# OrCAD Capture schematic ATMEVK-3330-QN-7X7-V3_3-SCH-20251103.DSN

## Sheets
1 10. Power Configuration: title: ATM3330e EVALUATION BOARD; rev: 3.3; note: 052-33-610-xxxx
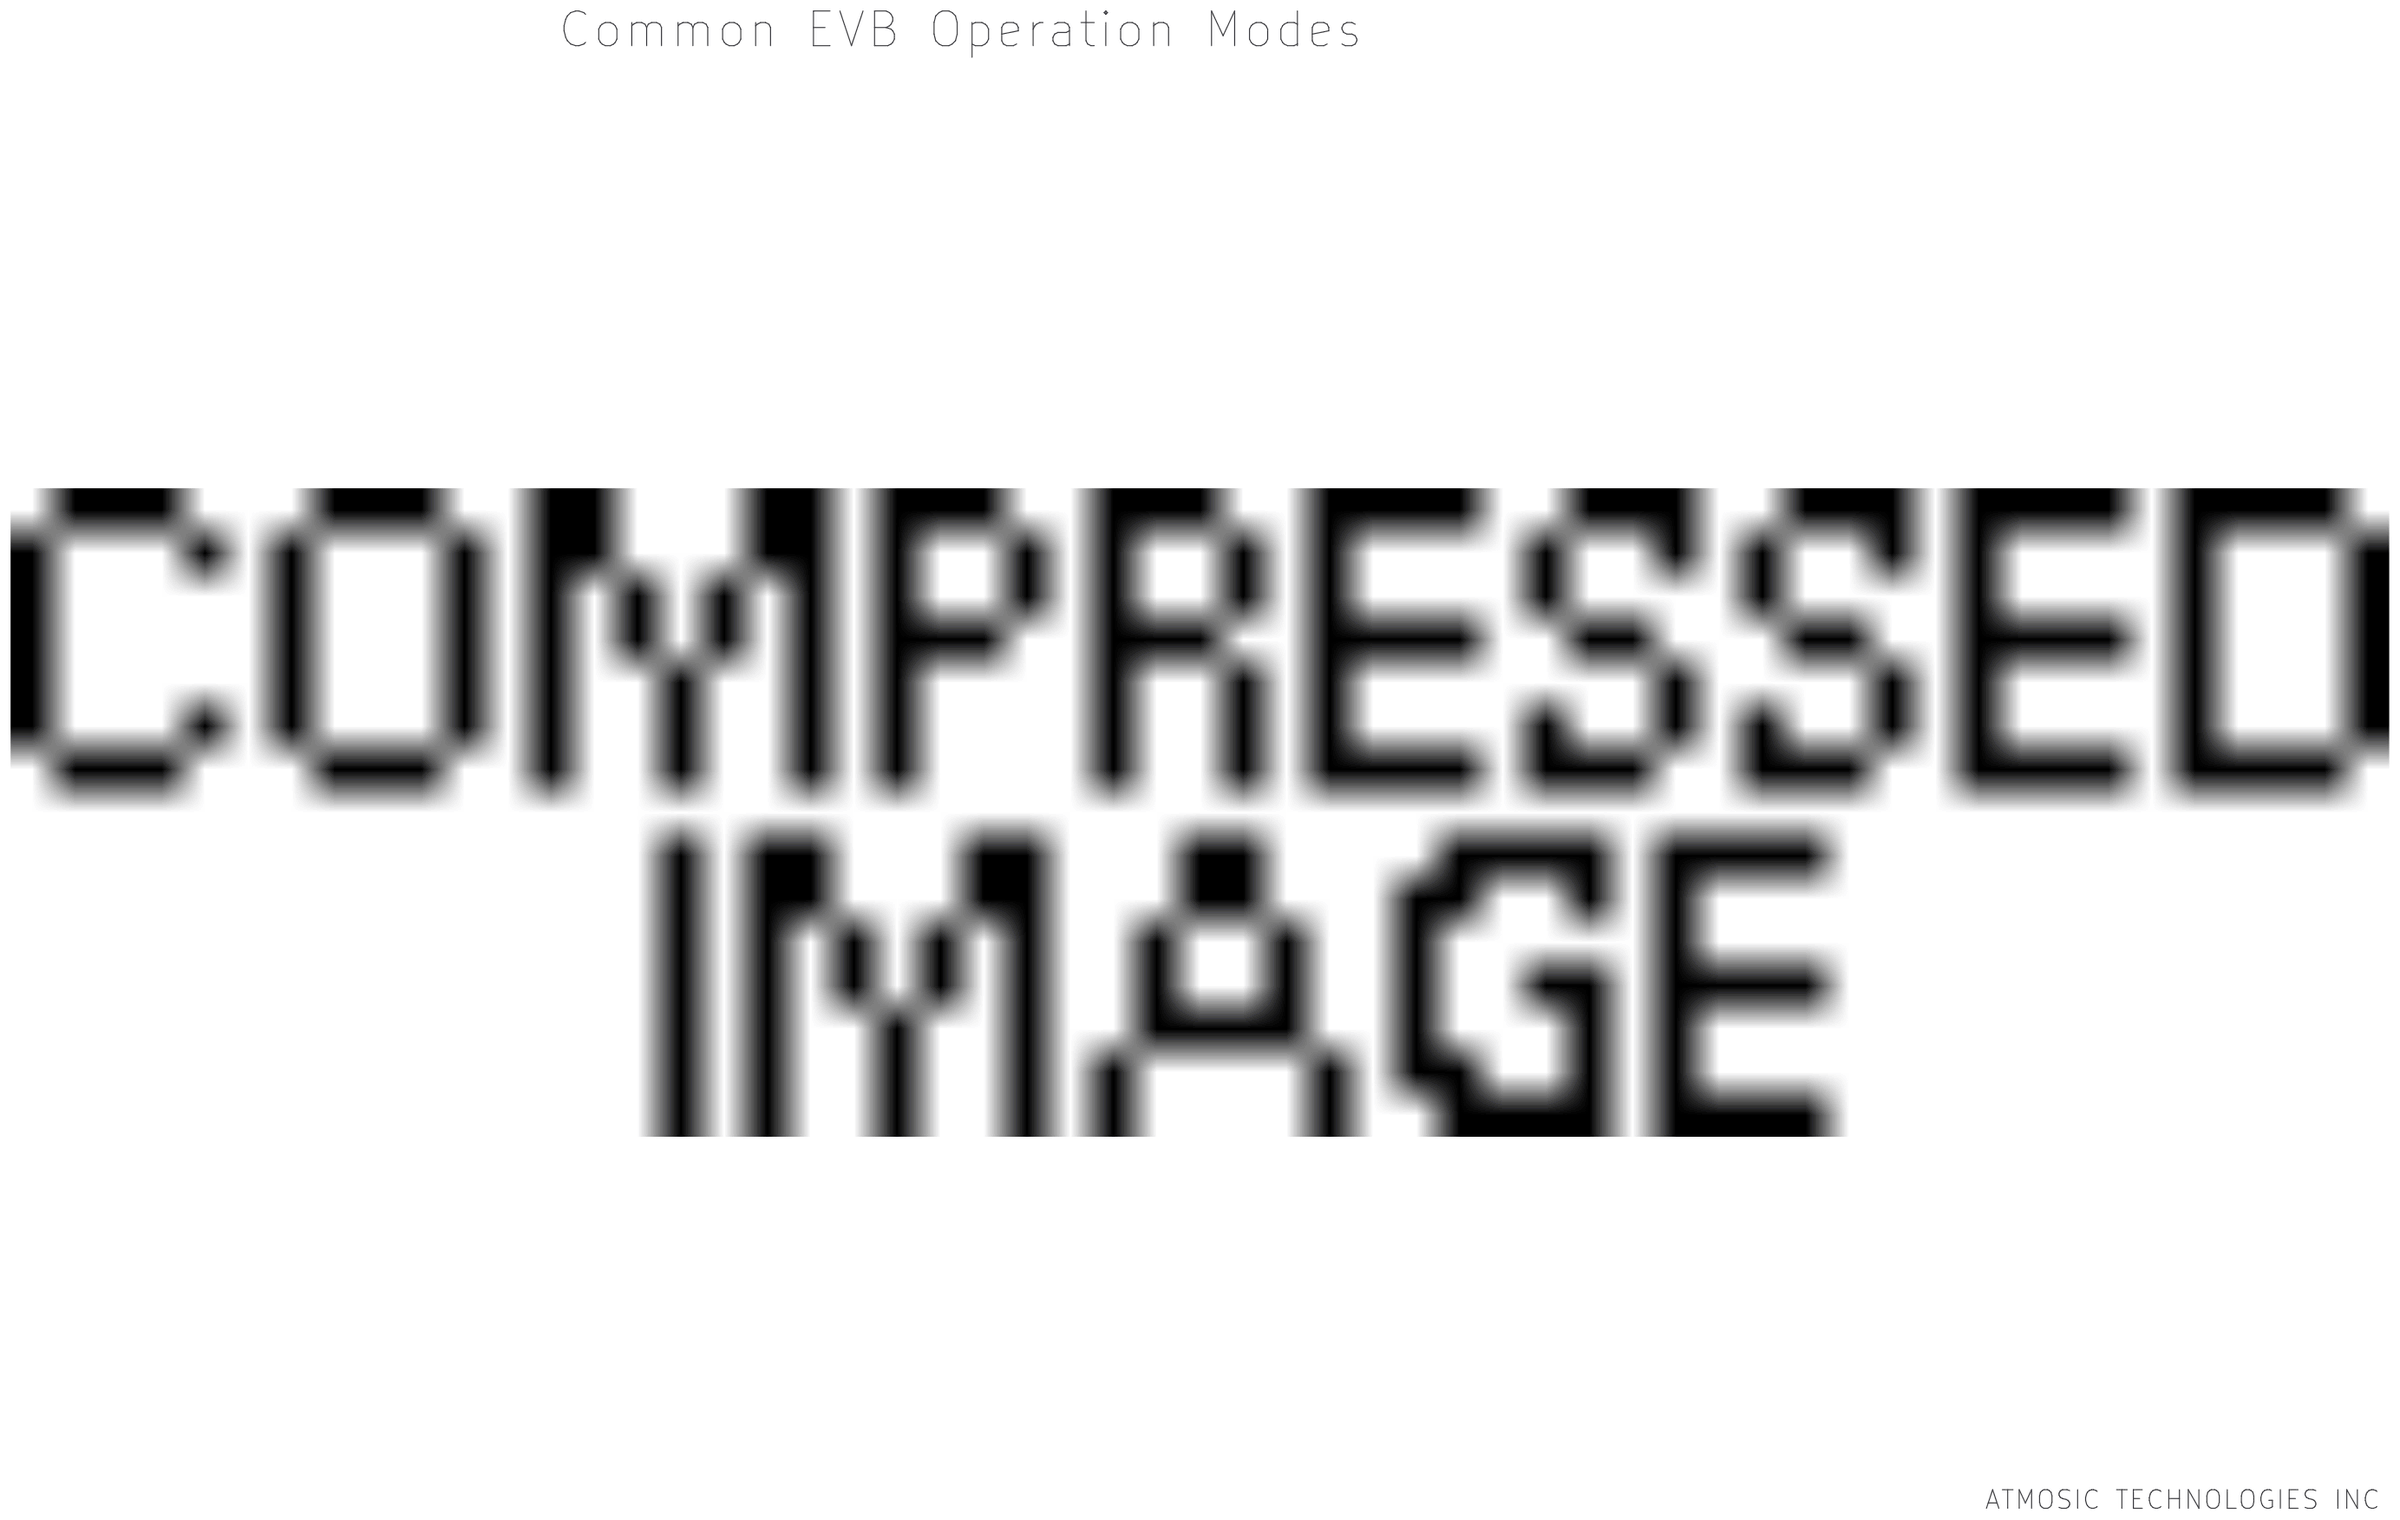
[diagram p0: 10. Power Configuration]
2 01. TITLE
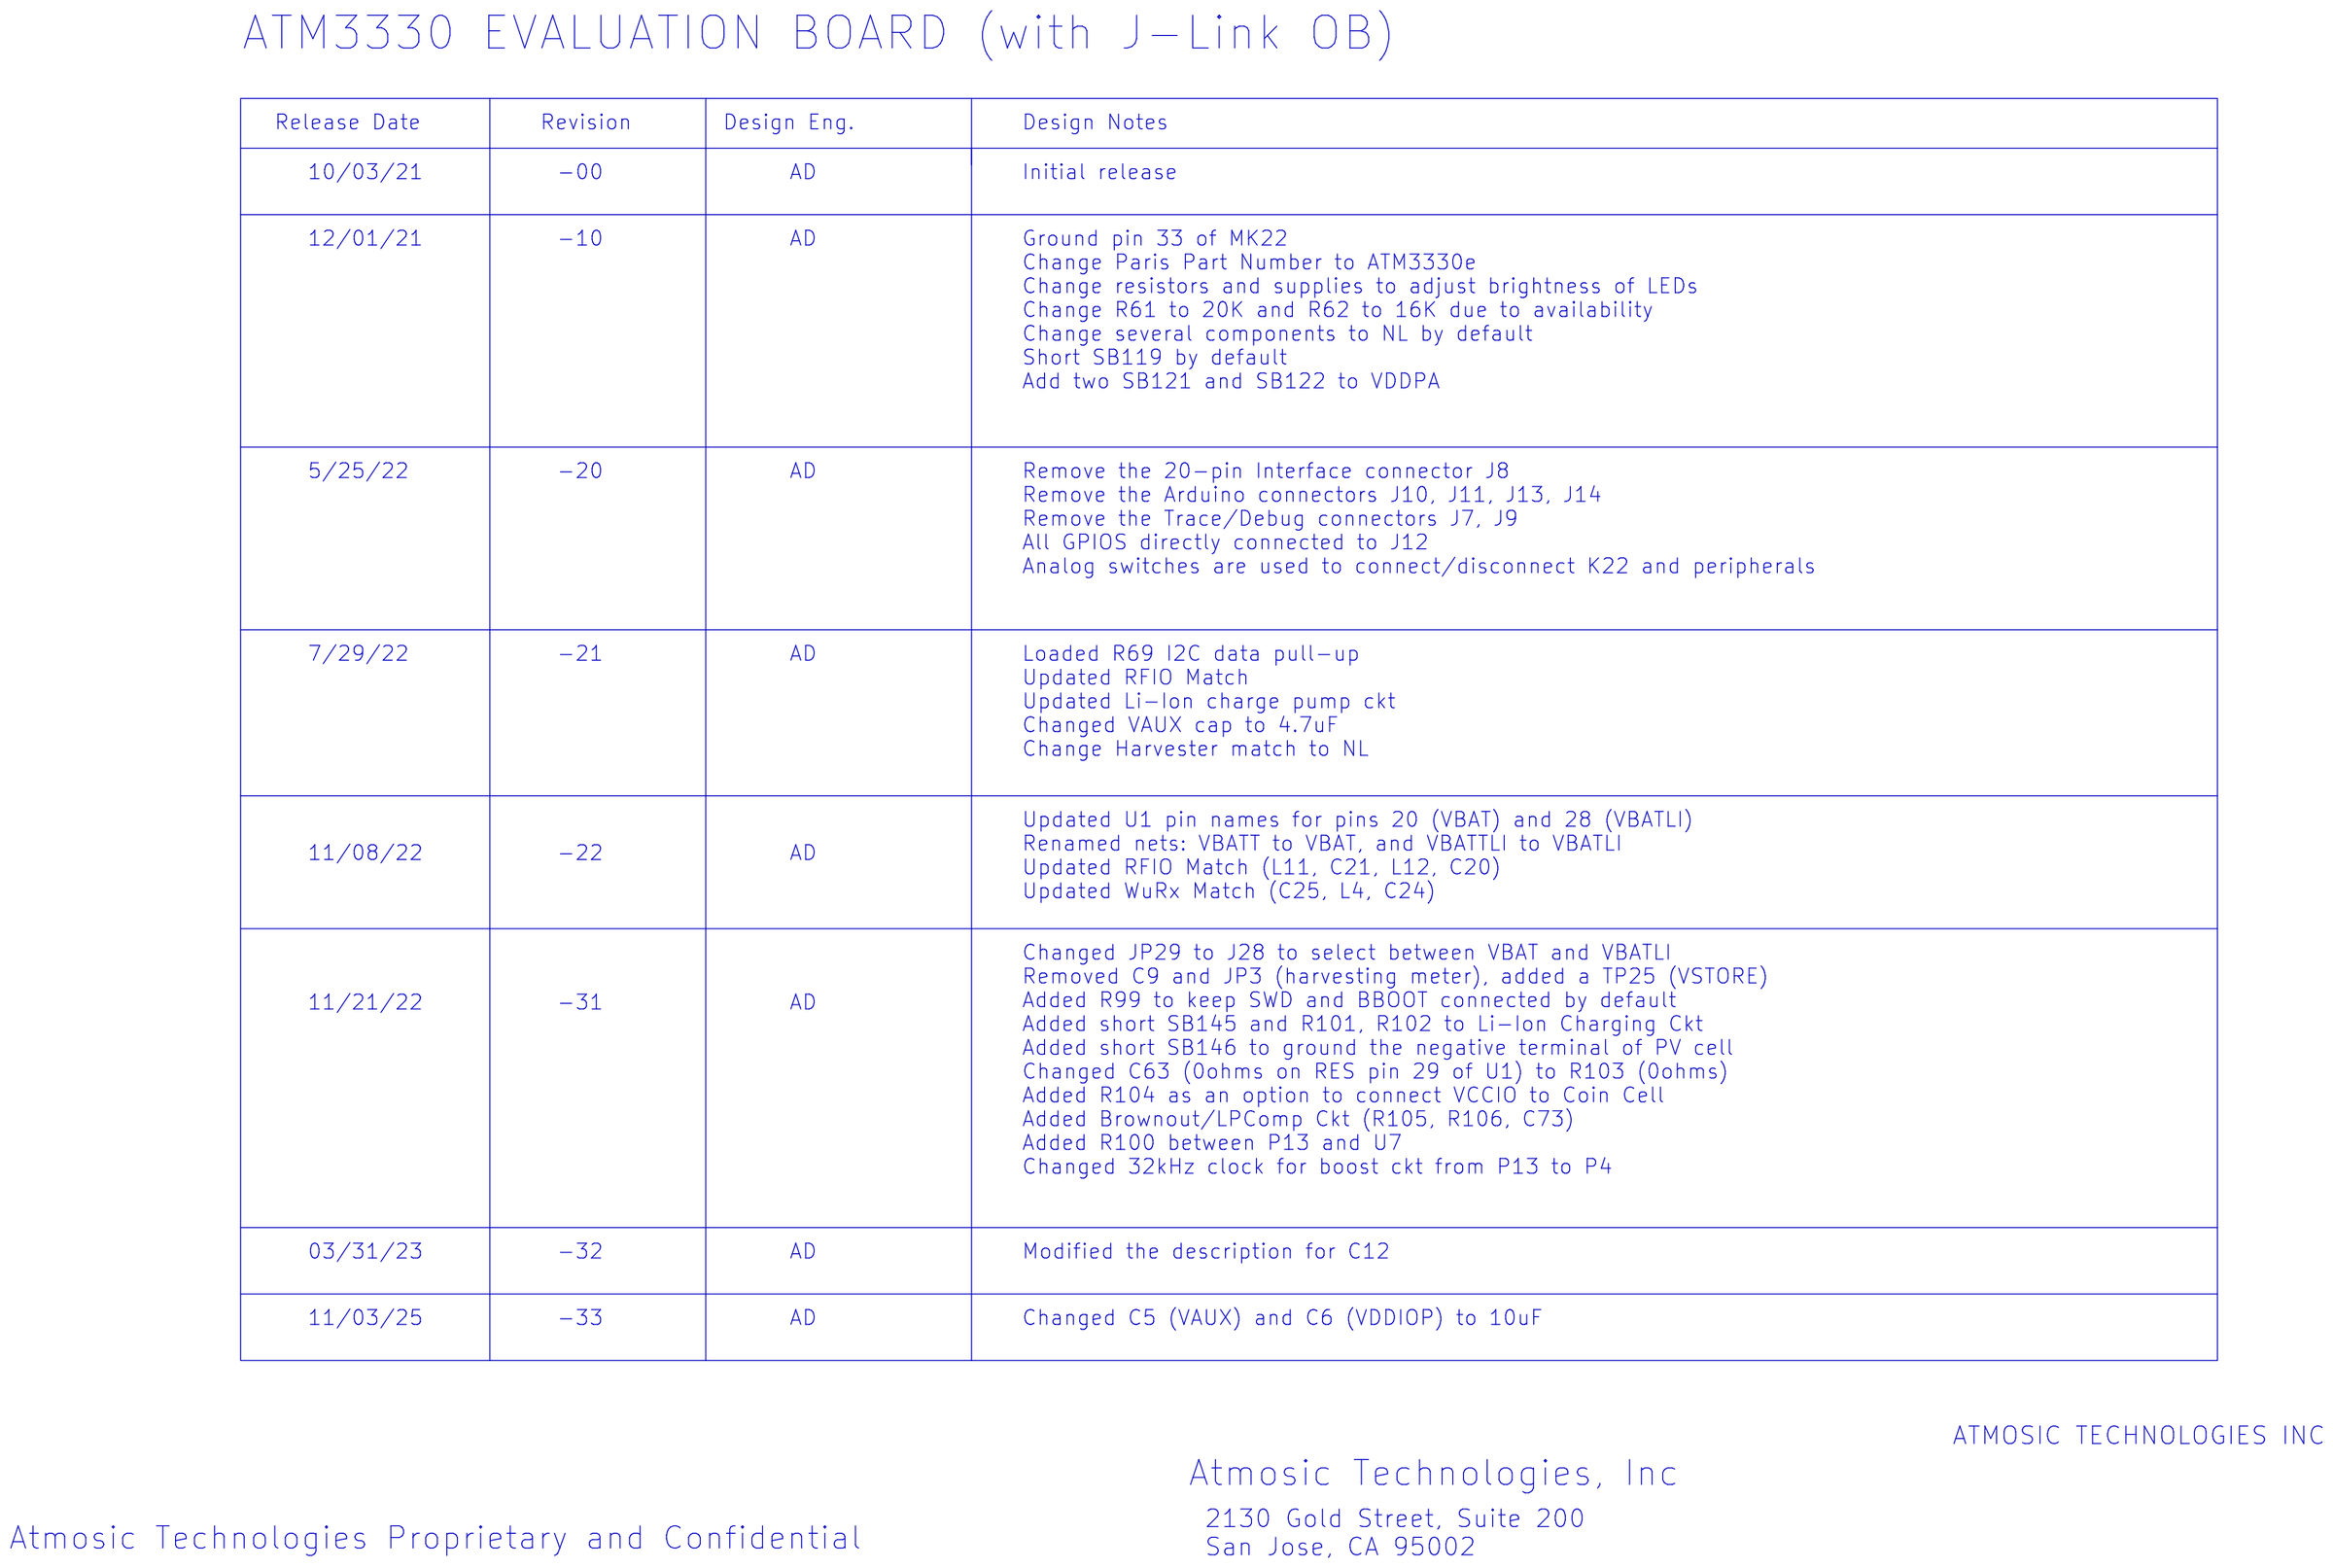
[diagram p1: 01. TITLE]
3 02. Block Diagram
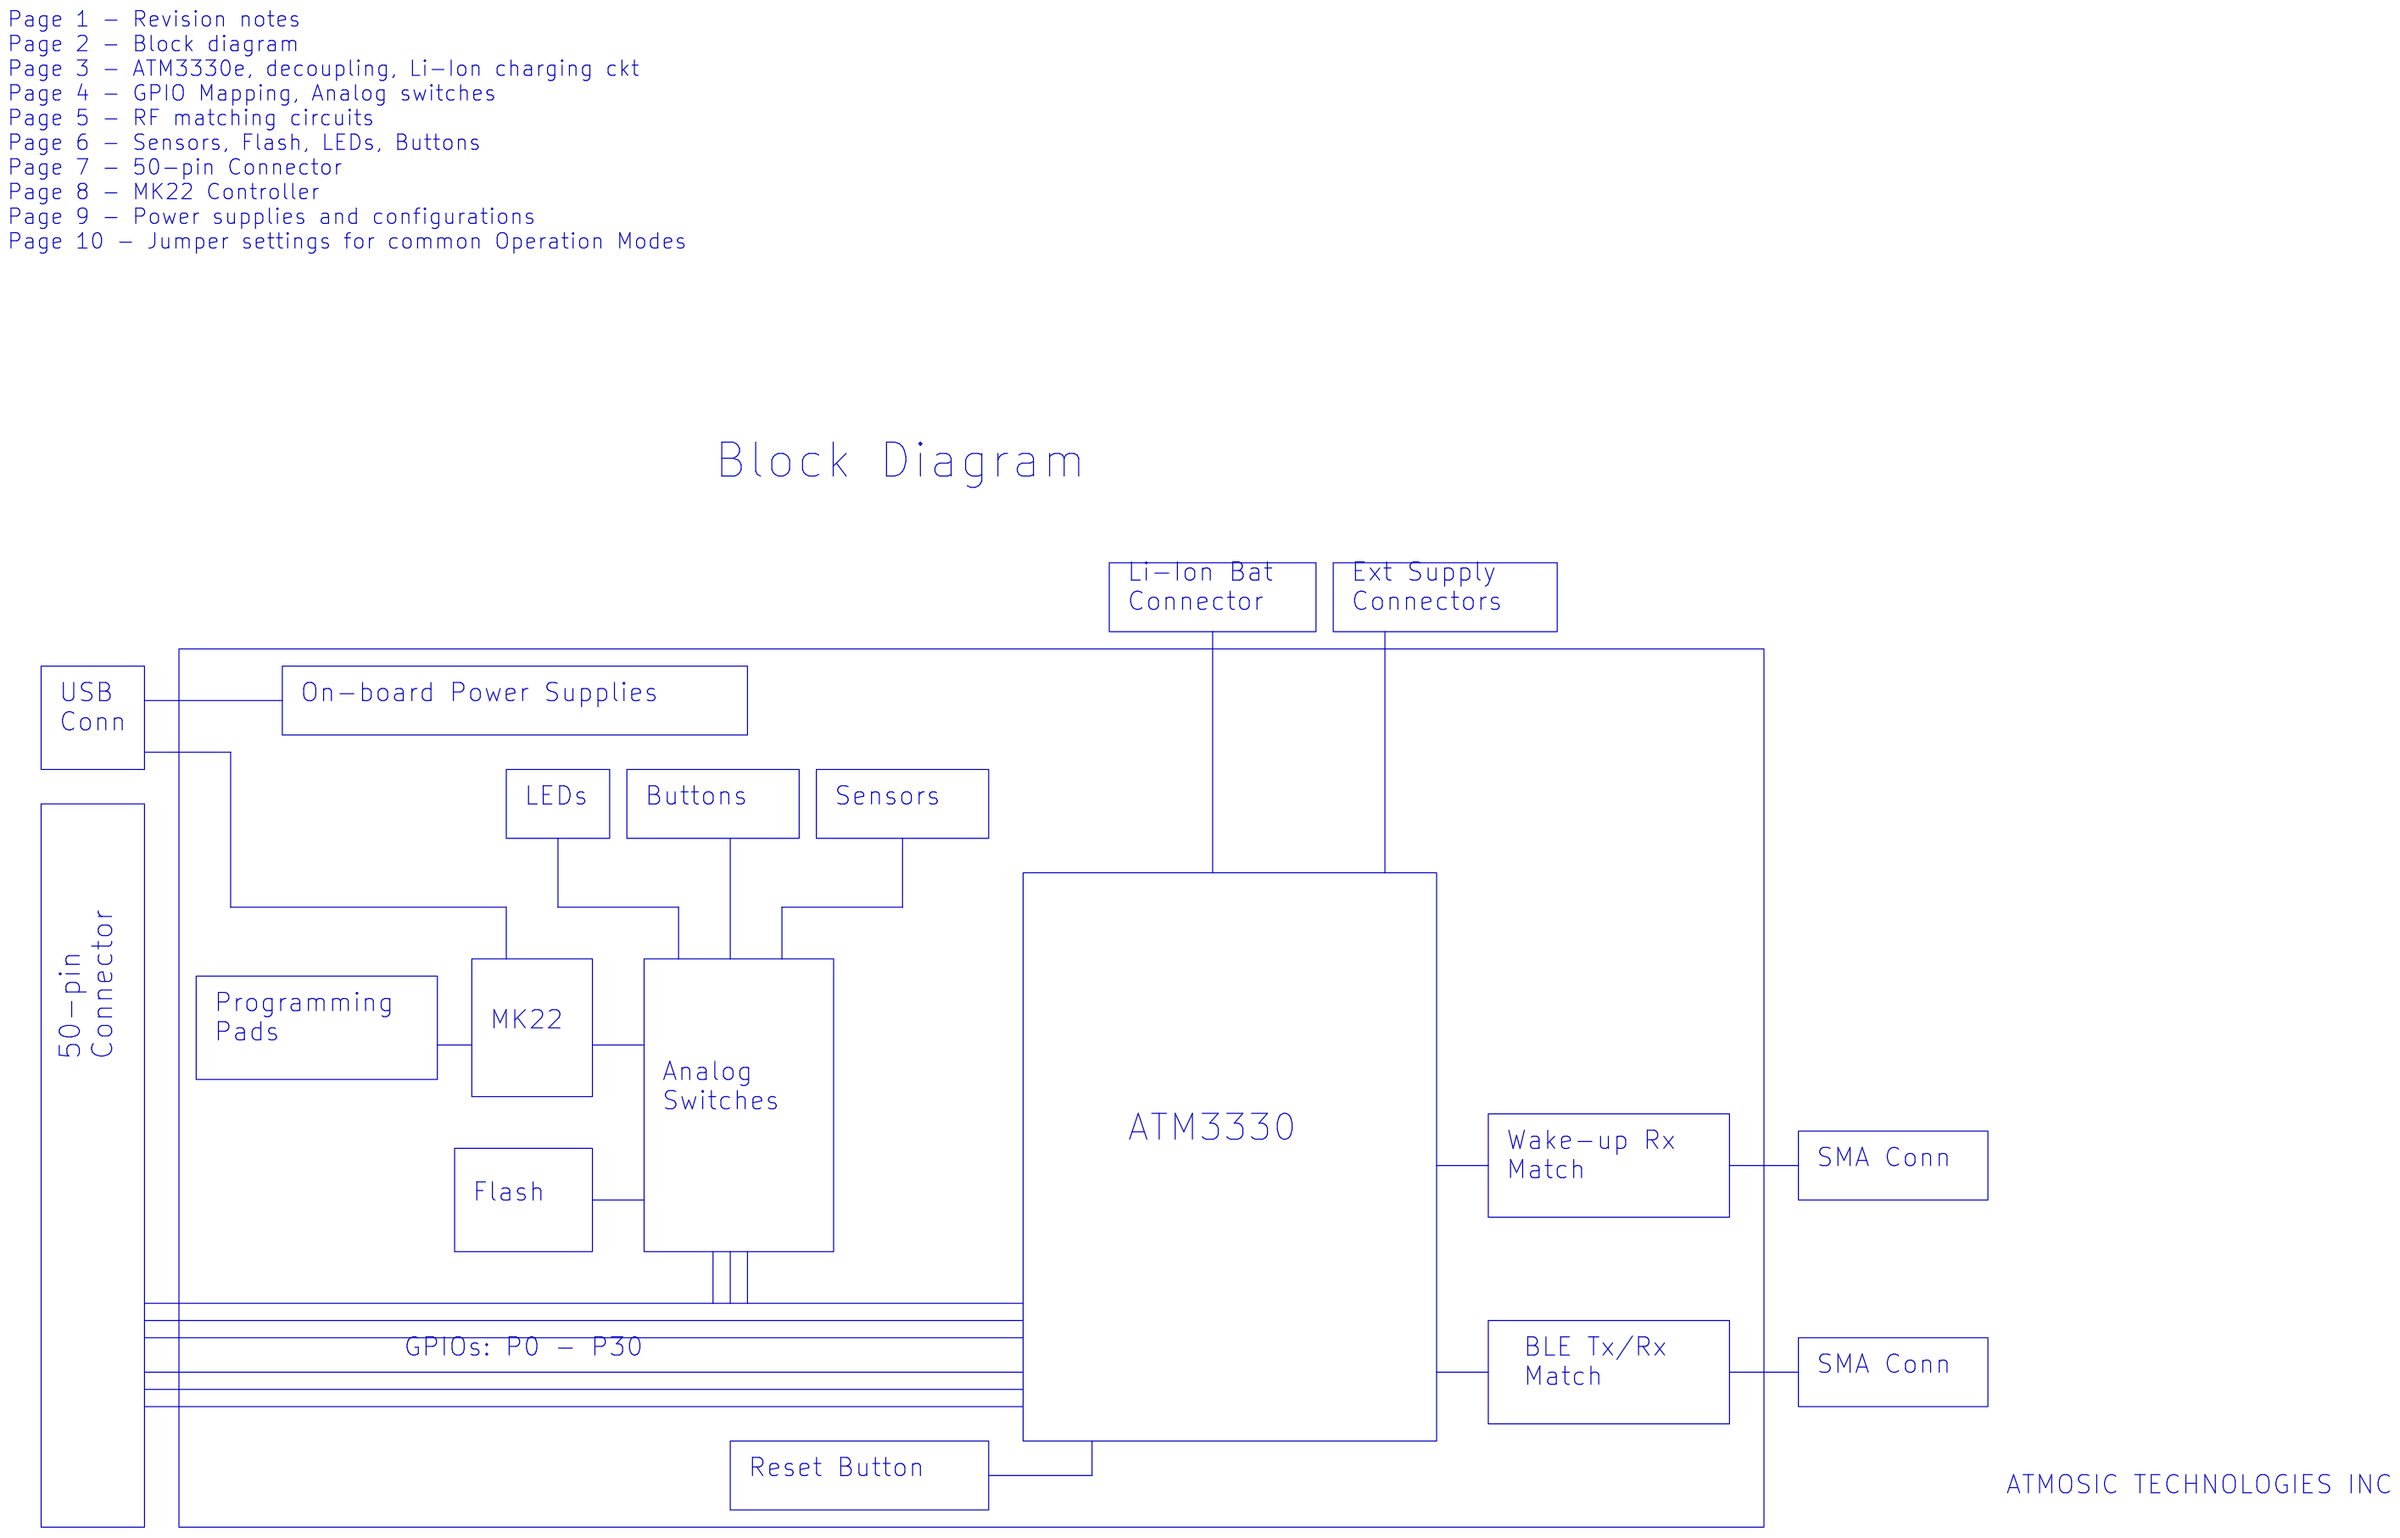
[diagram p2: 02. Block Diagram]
4 03. ATM3330: size B
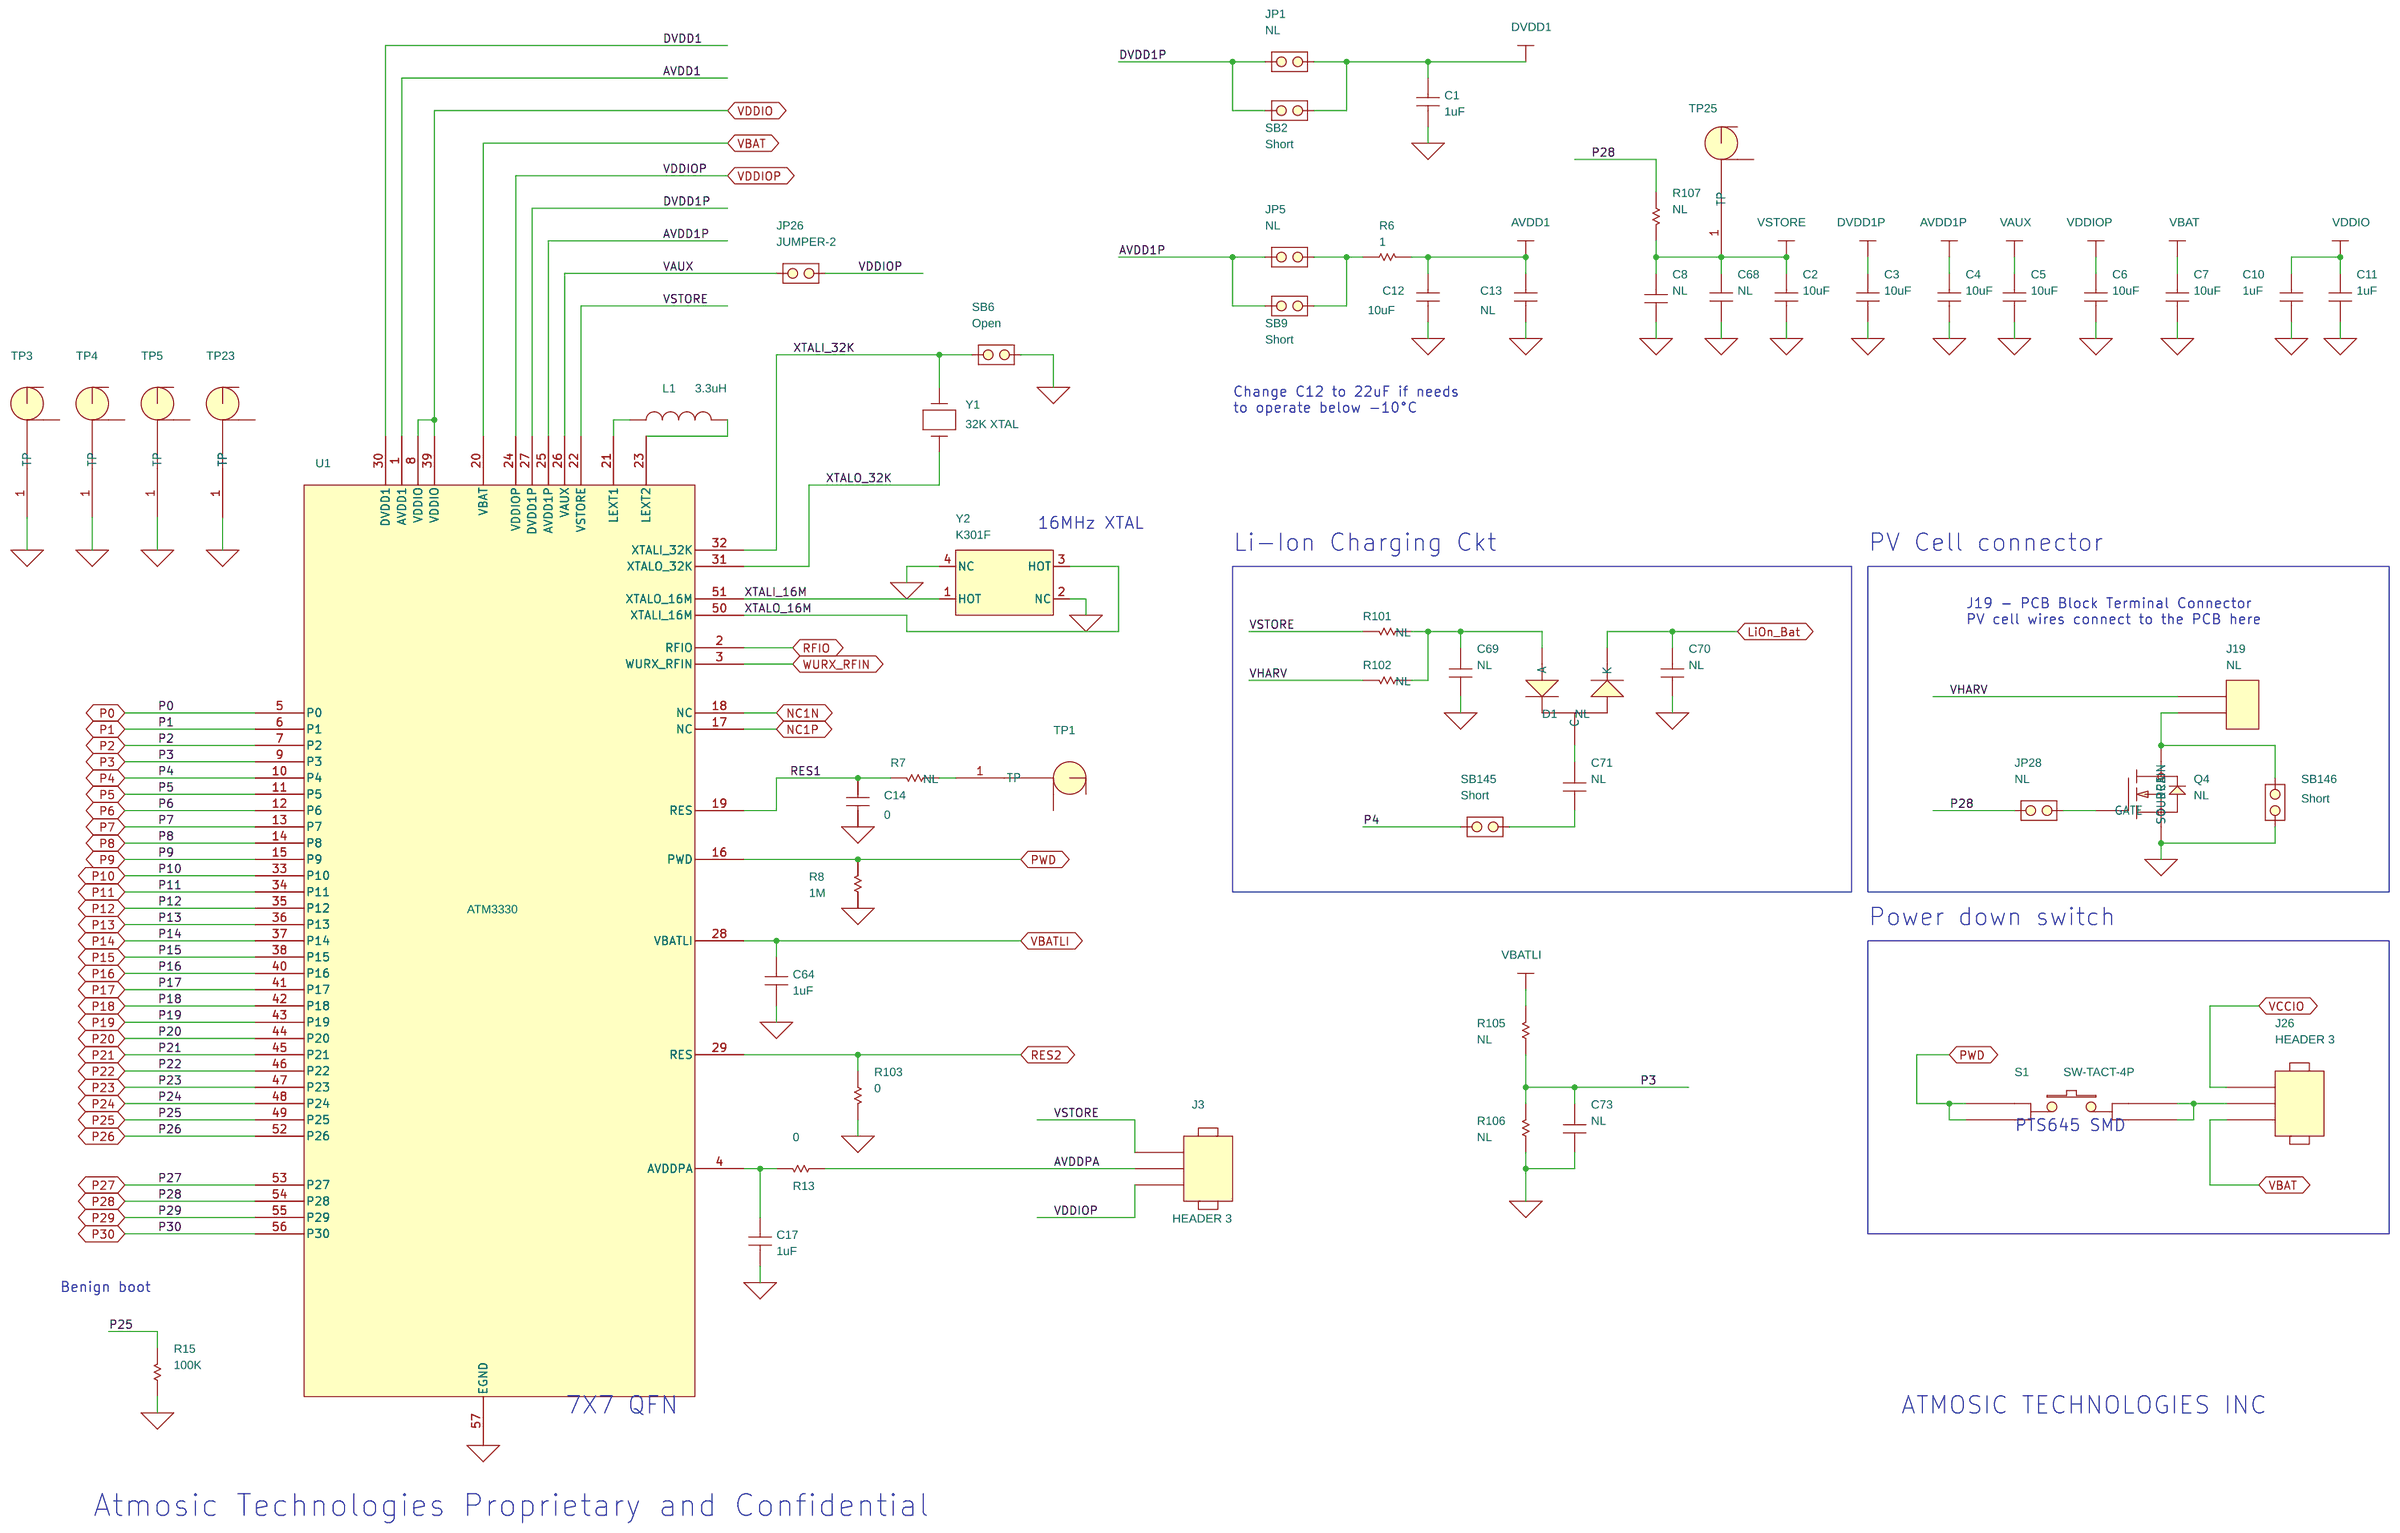
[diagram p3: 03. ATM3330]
5 04. GPIO Mapping: size B
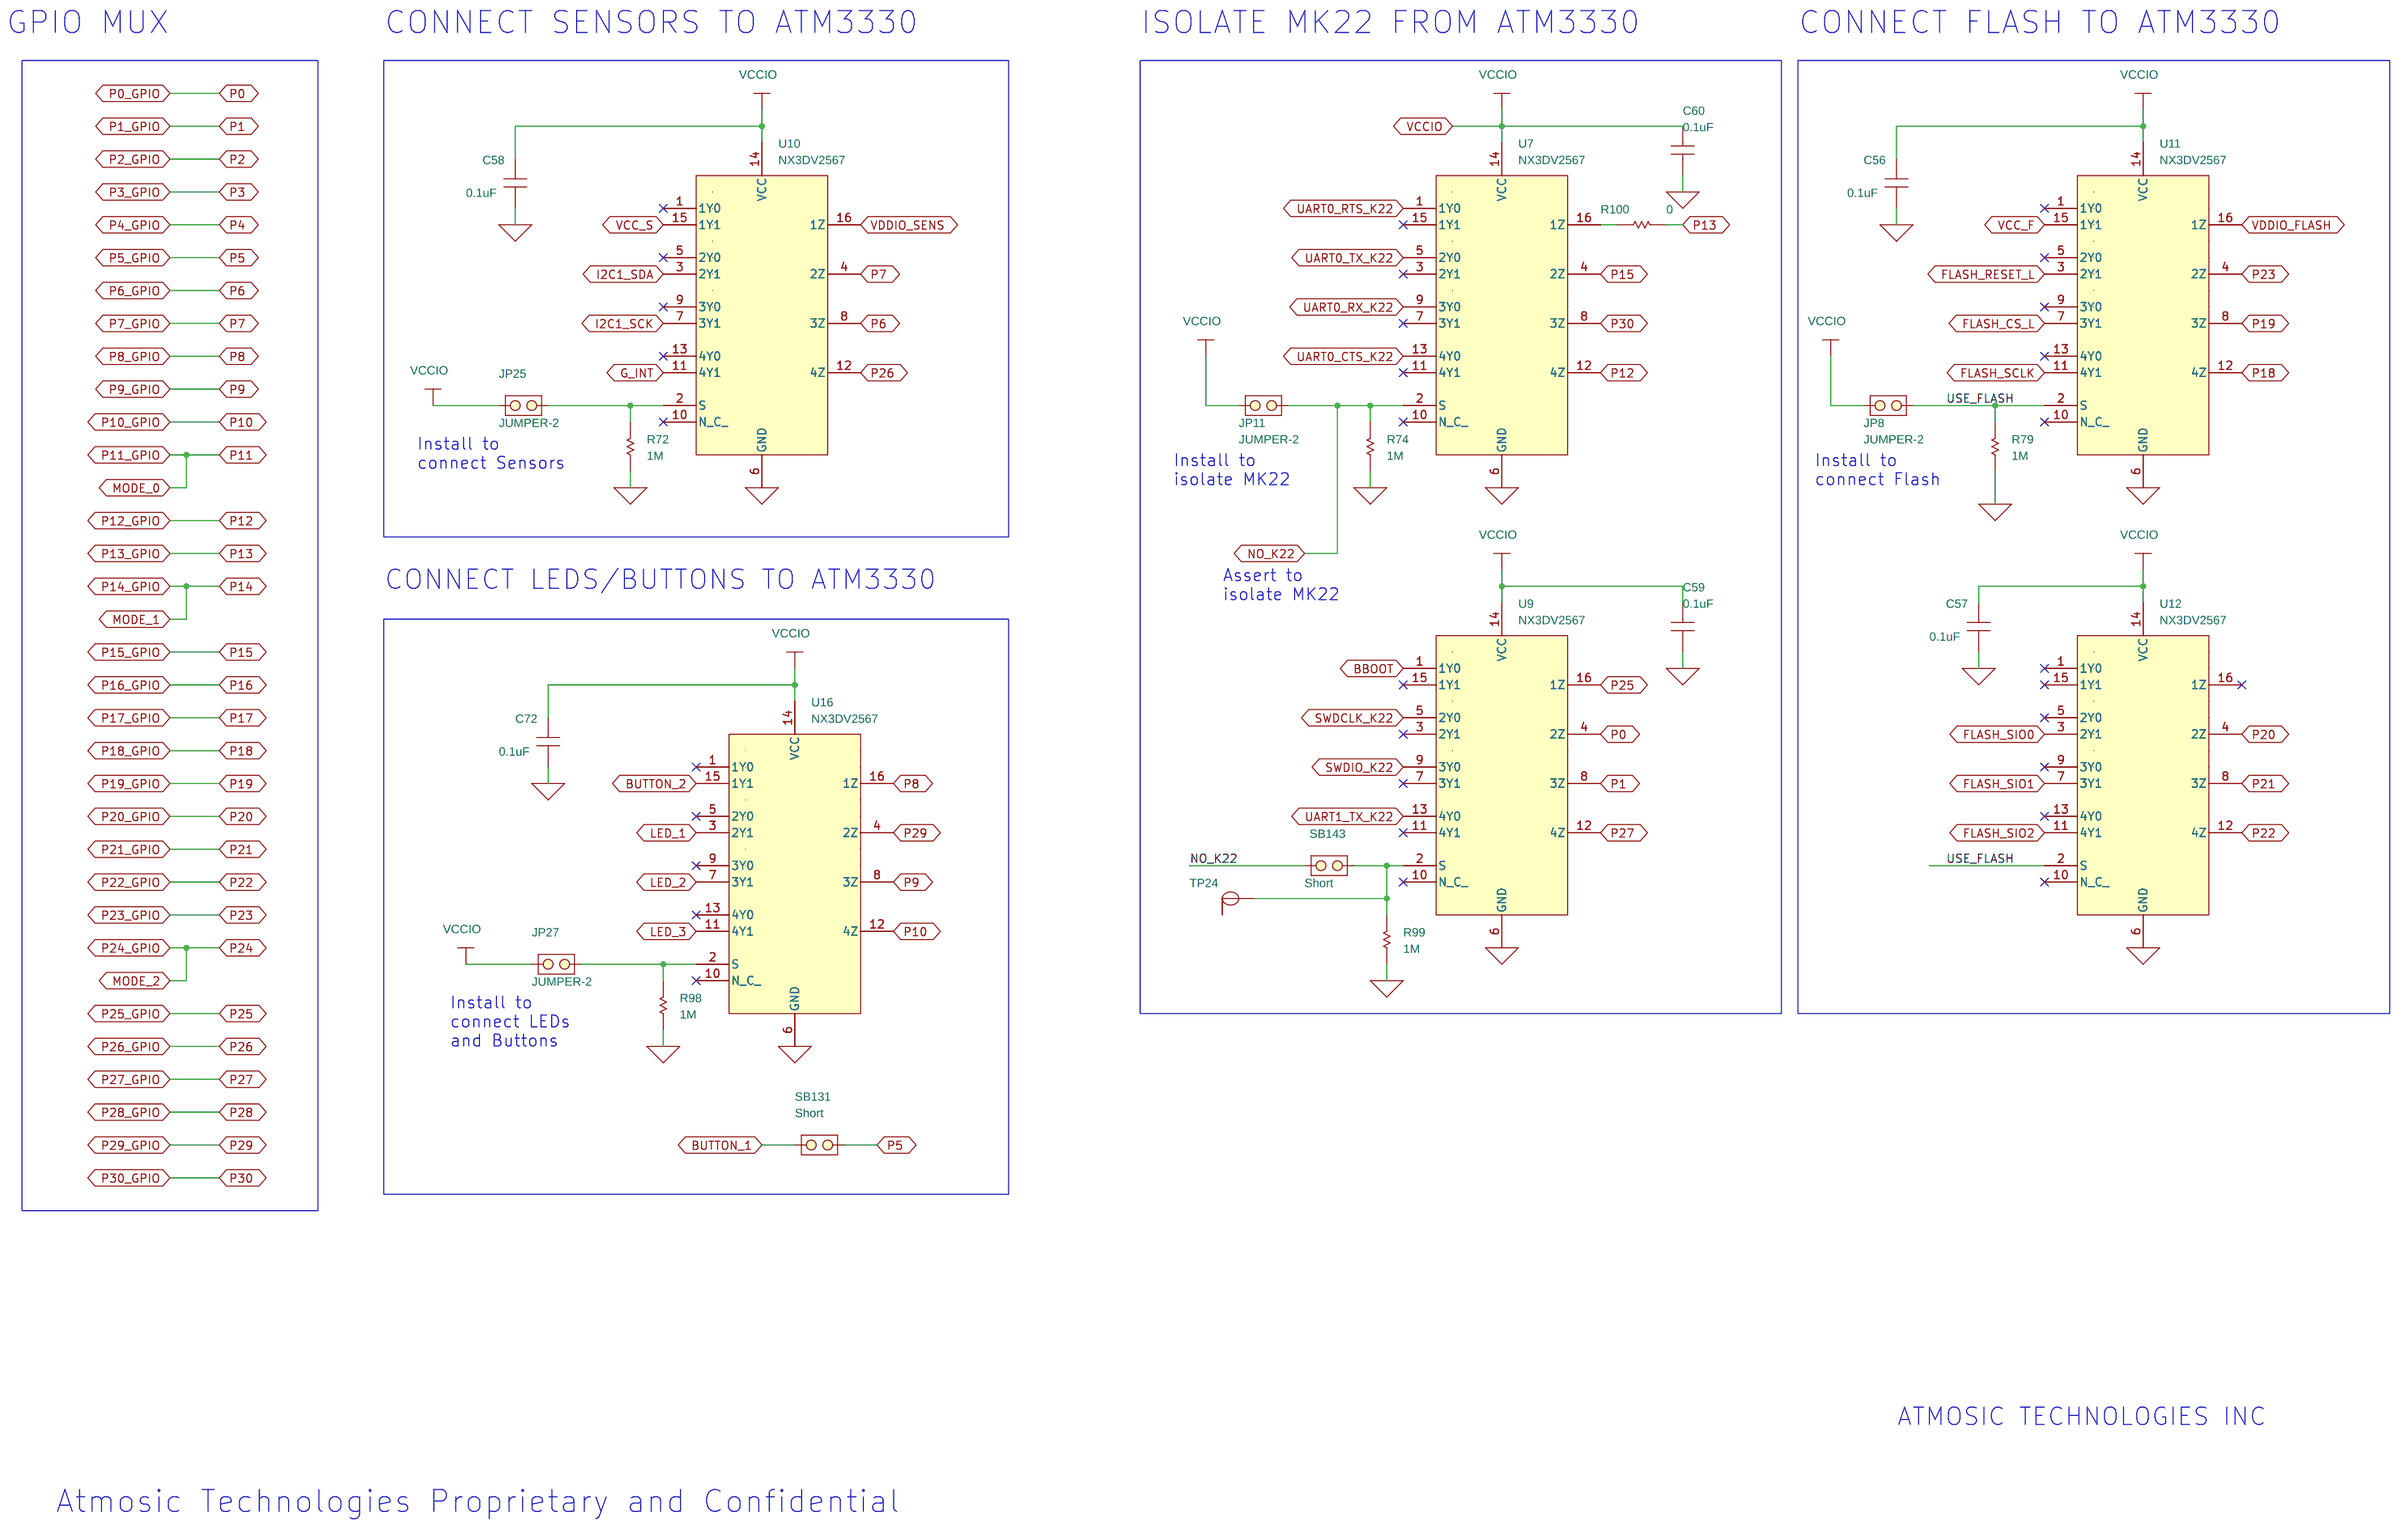
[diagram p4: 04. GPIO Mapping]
6 06. Buttons LEDs Sensors: size B
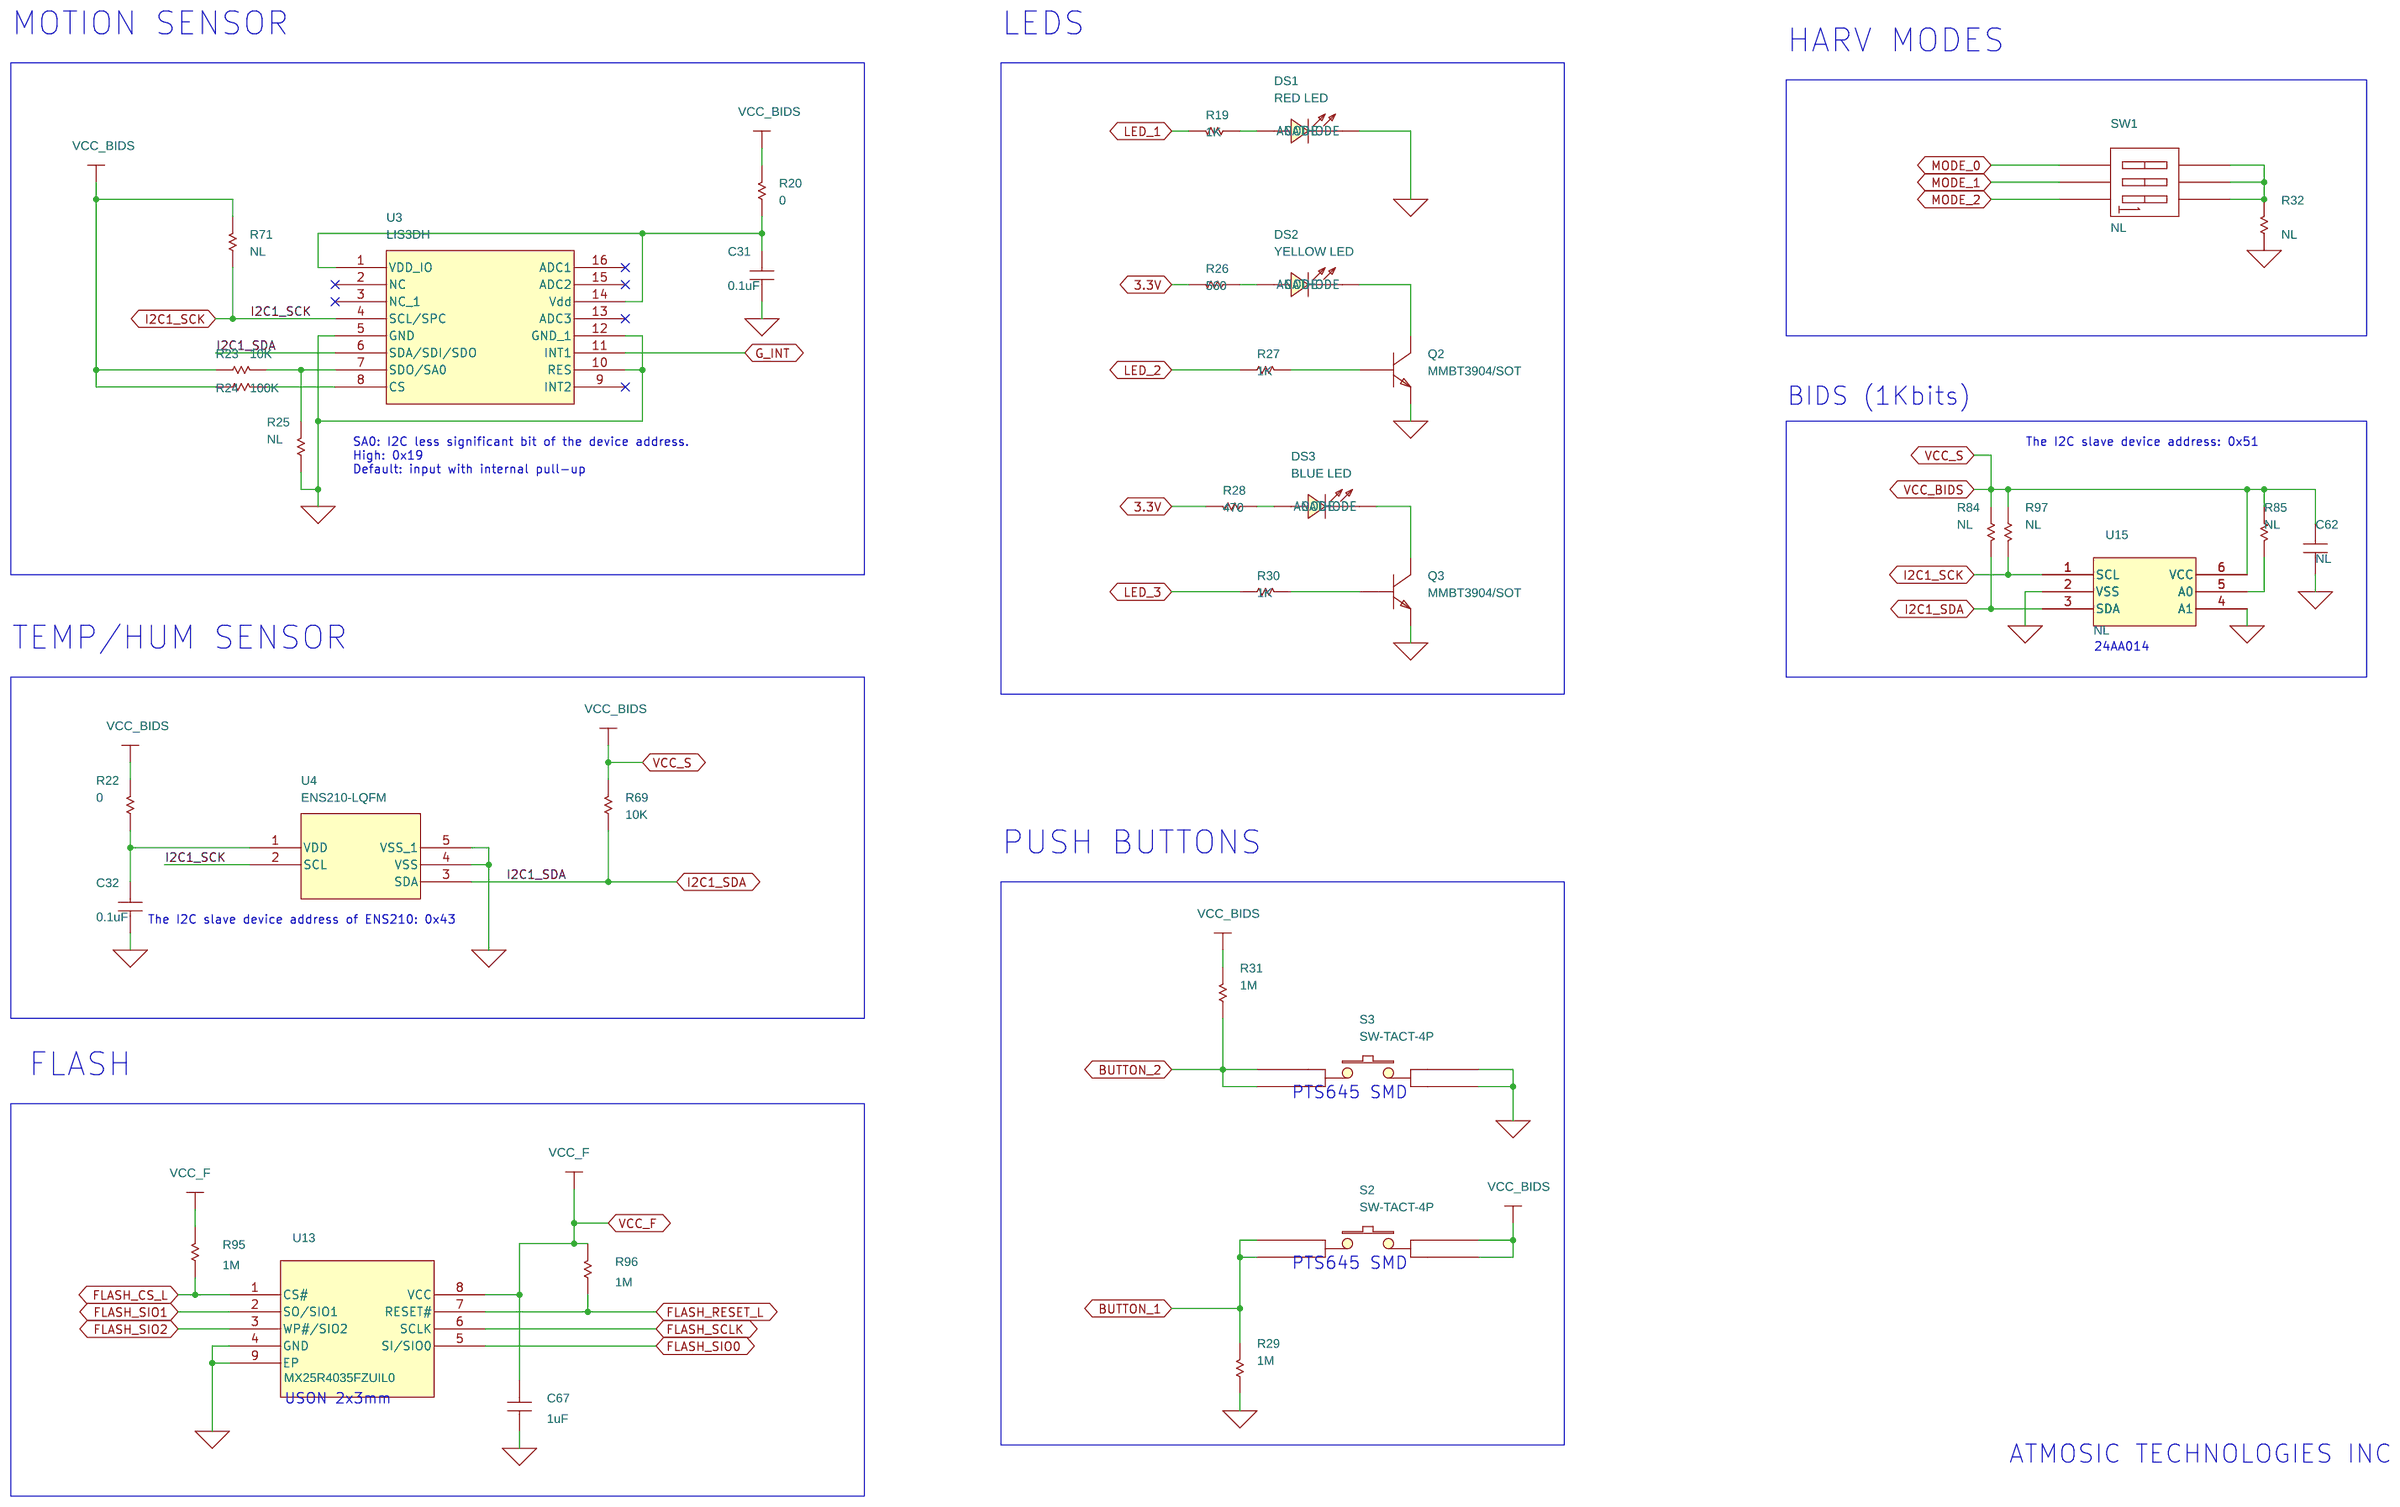
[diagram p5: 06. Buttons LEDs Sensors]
7 07. Connectors: size B
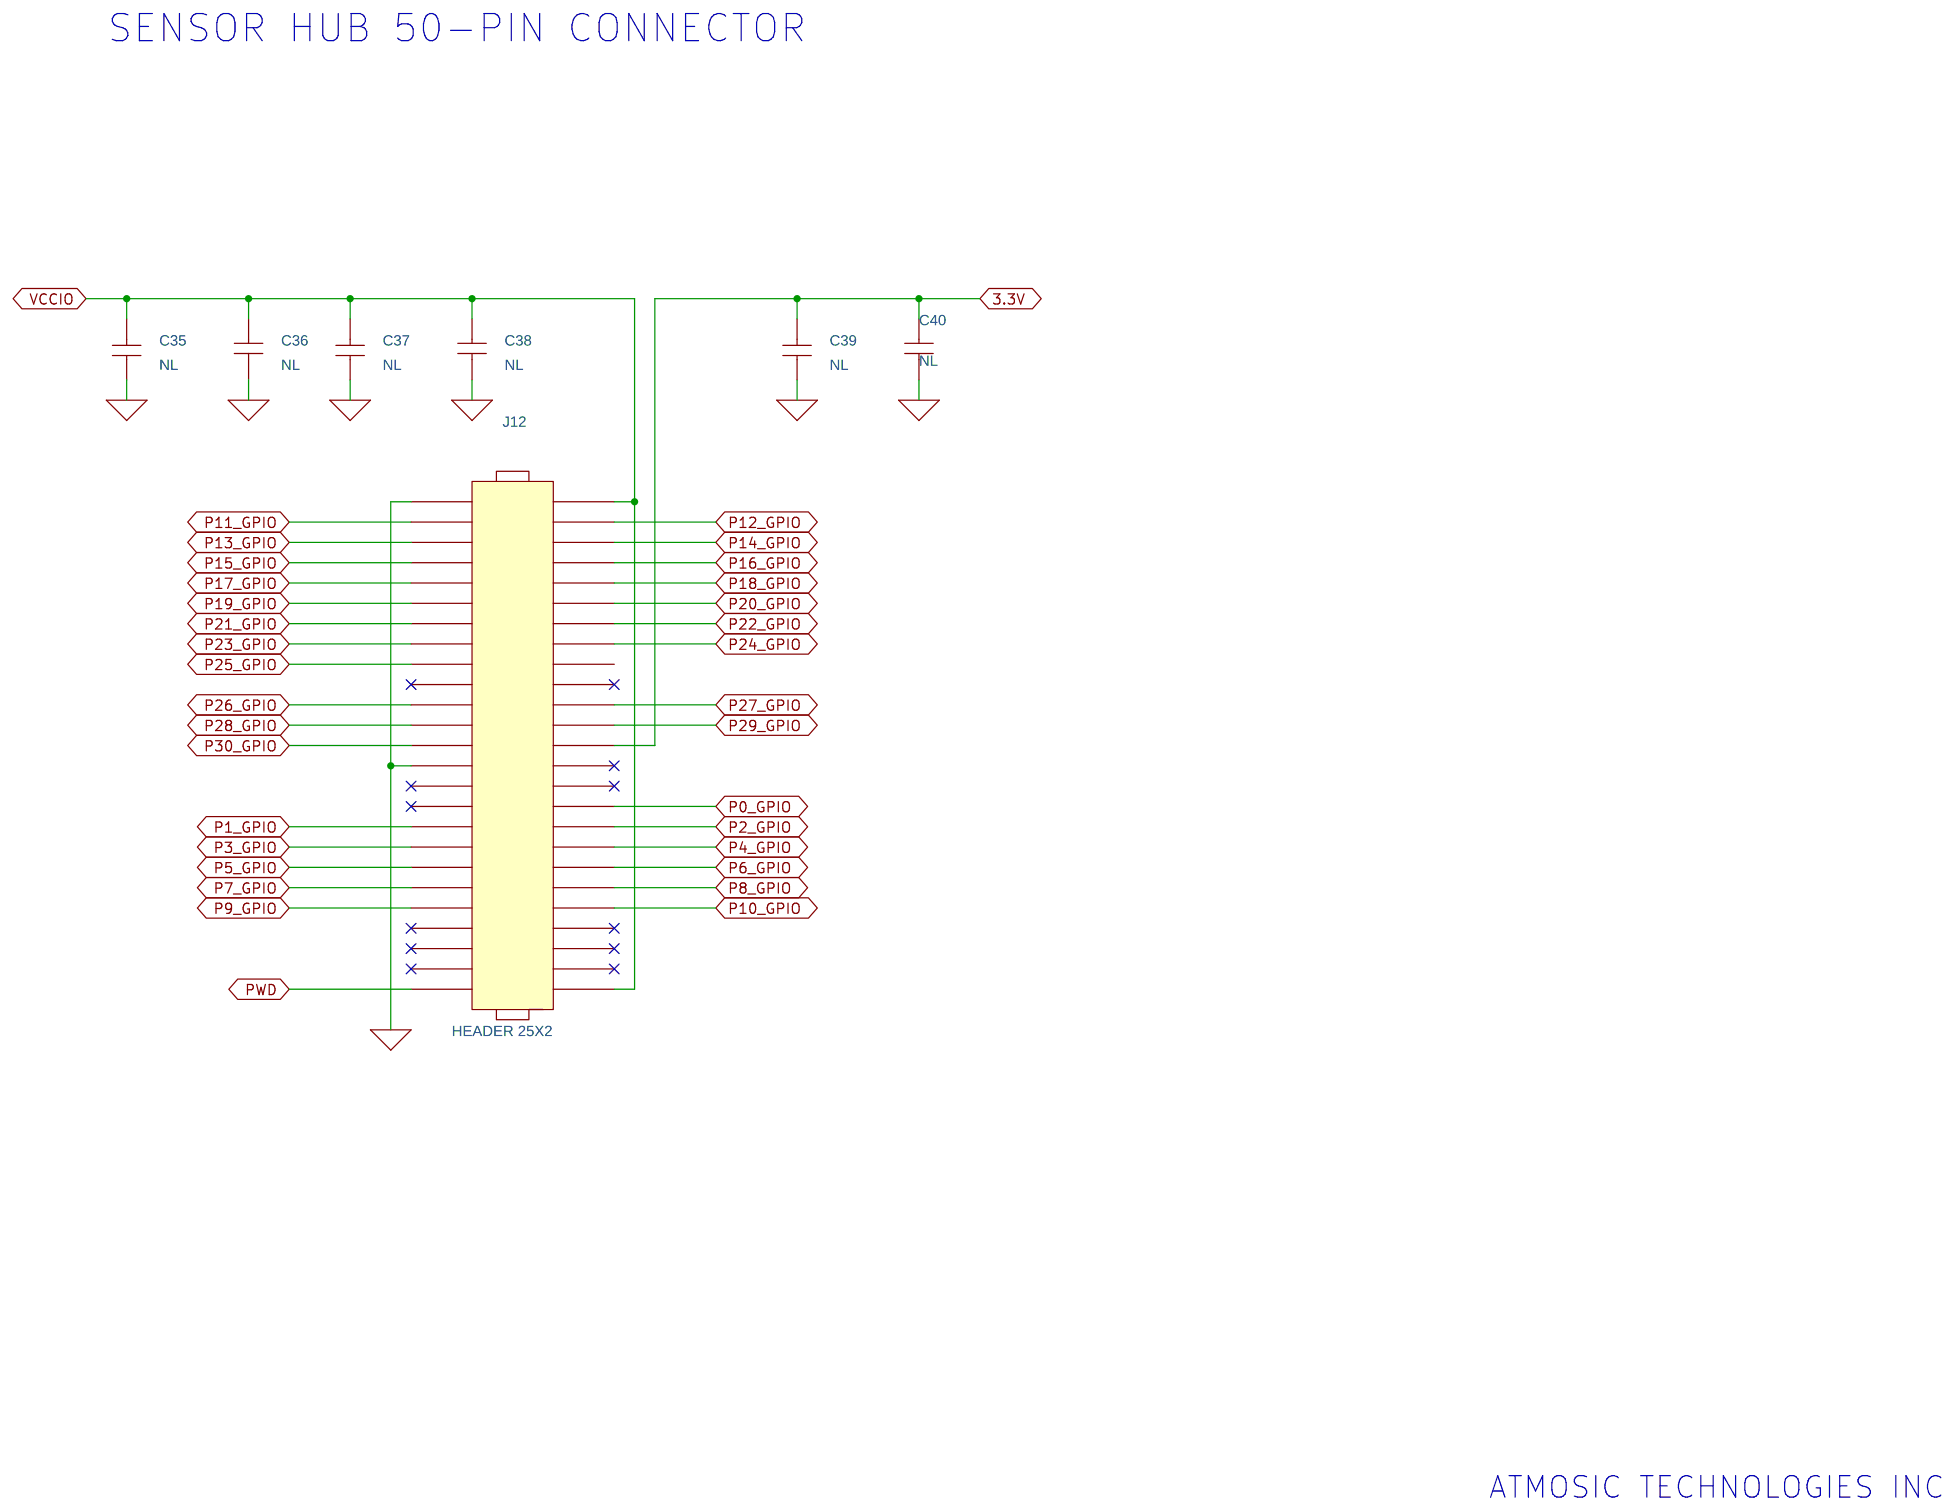
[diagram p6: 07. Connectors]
8 08. MK22: size B
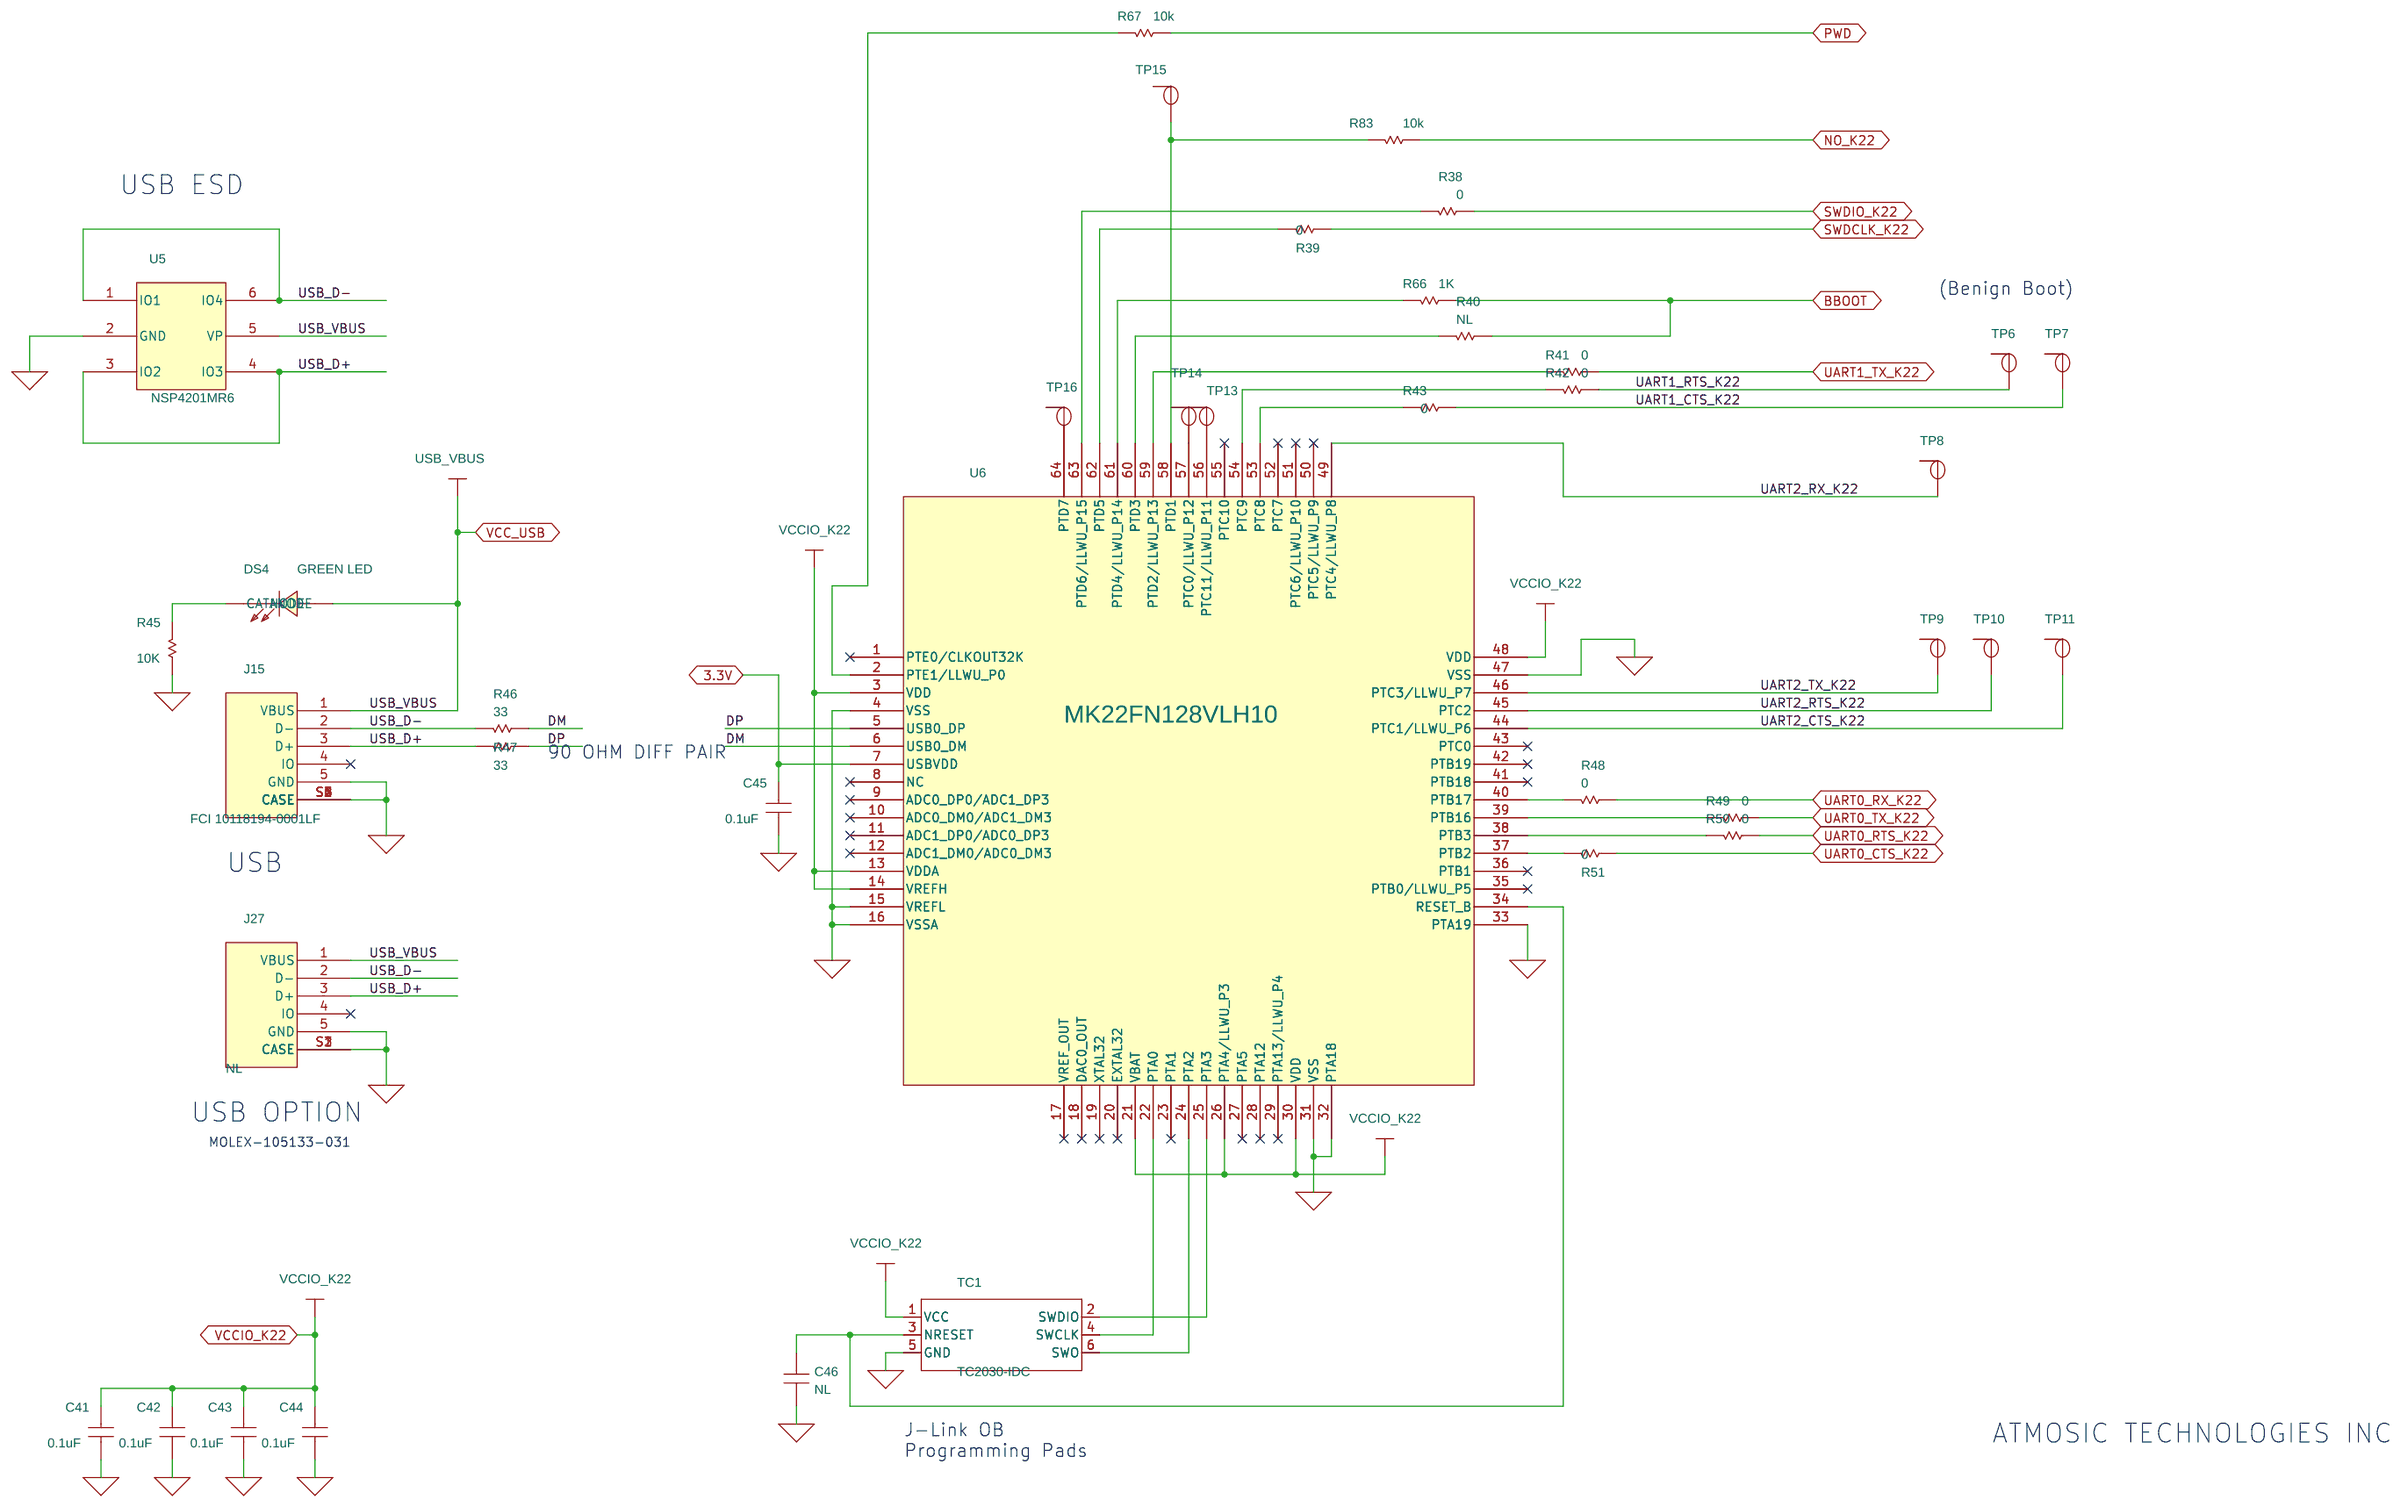
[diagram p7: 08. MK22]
9 09. Power: size B
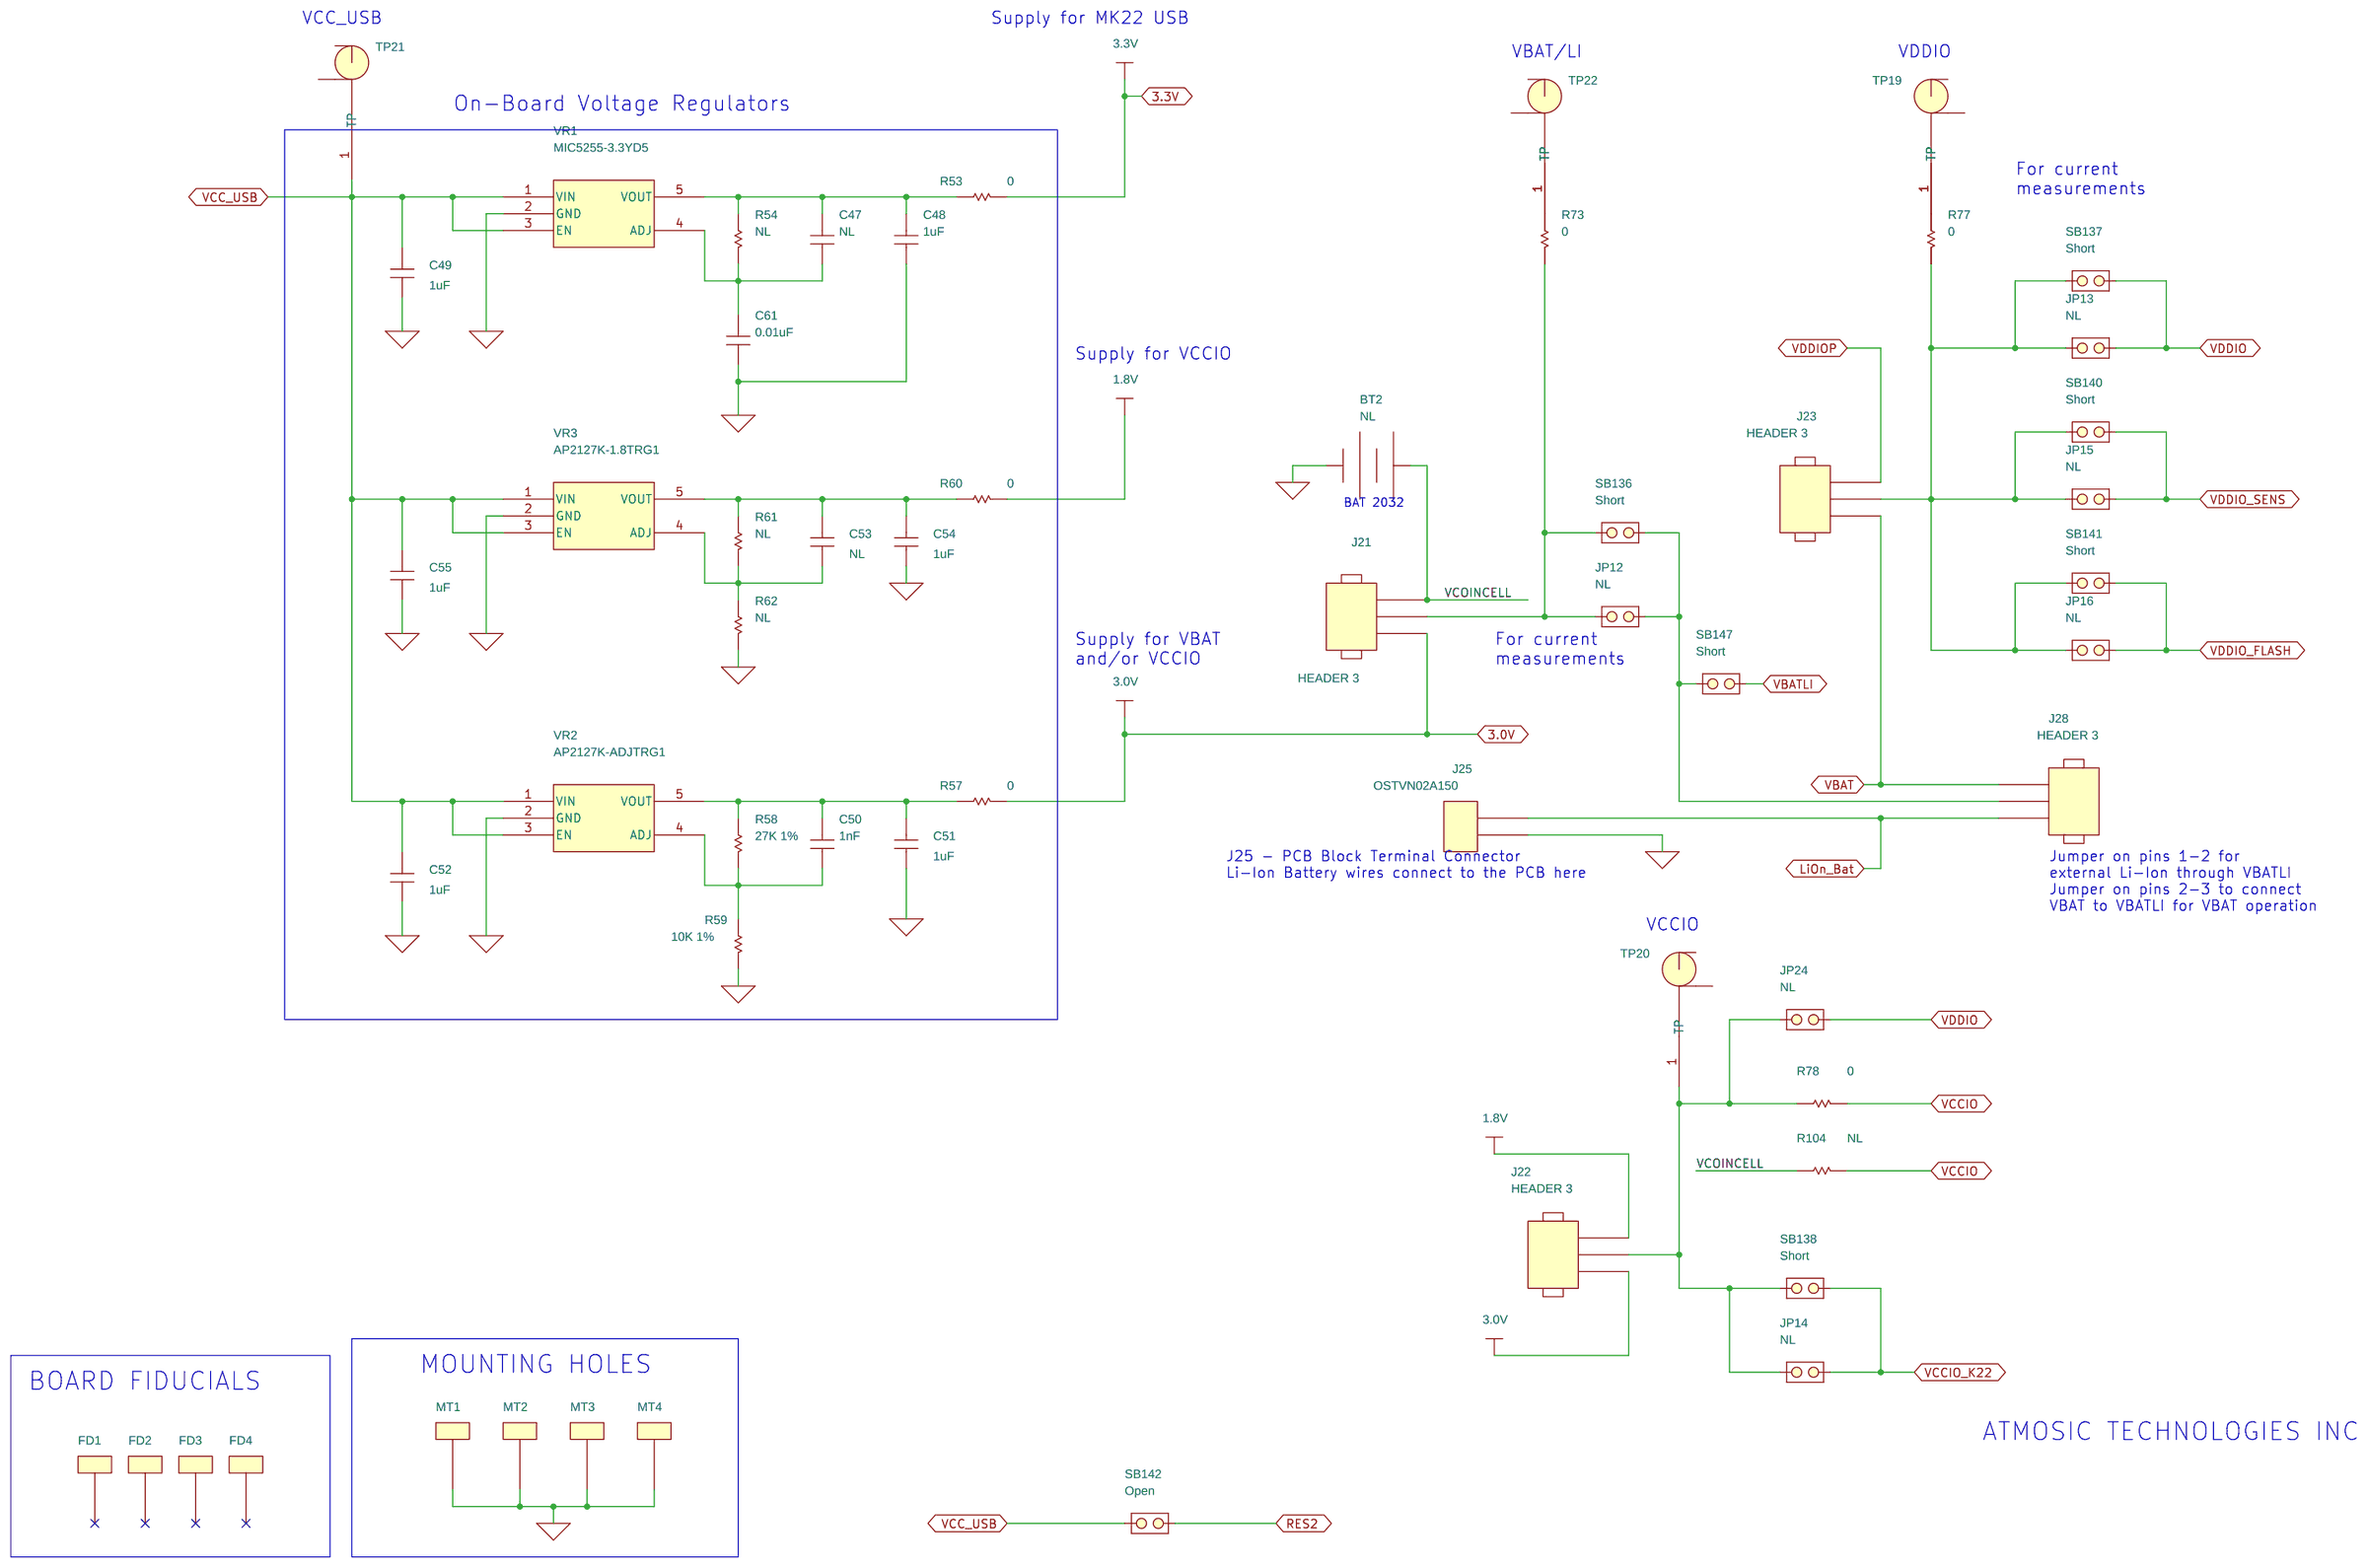
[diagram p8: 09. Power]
10 05. RF (RFIO/WuRX/HARV): size B
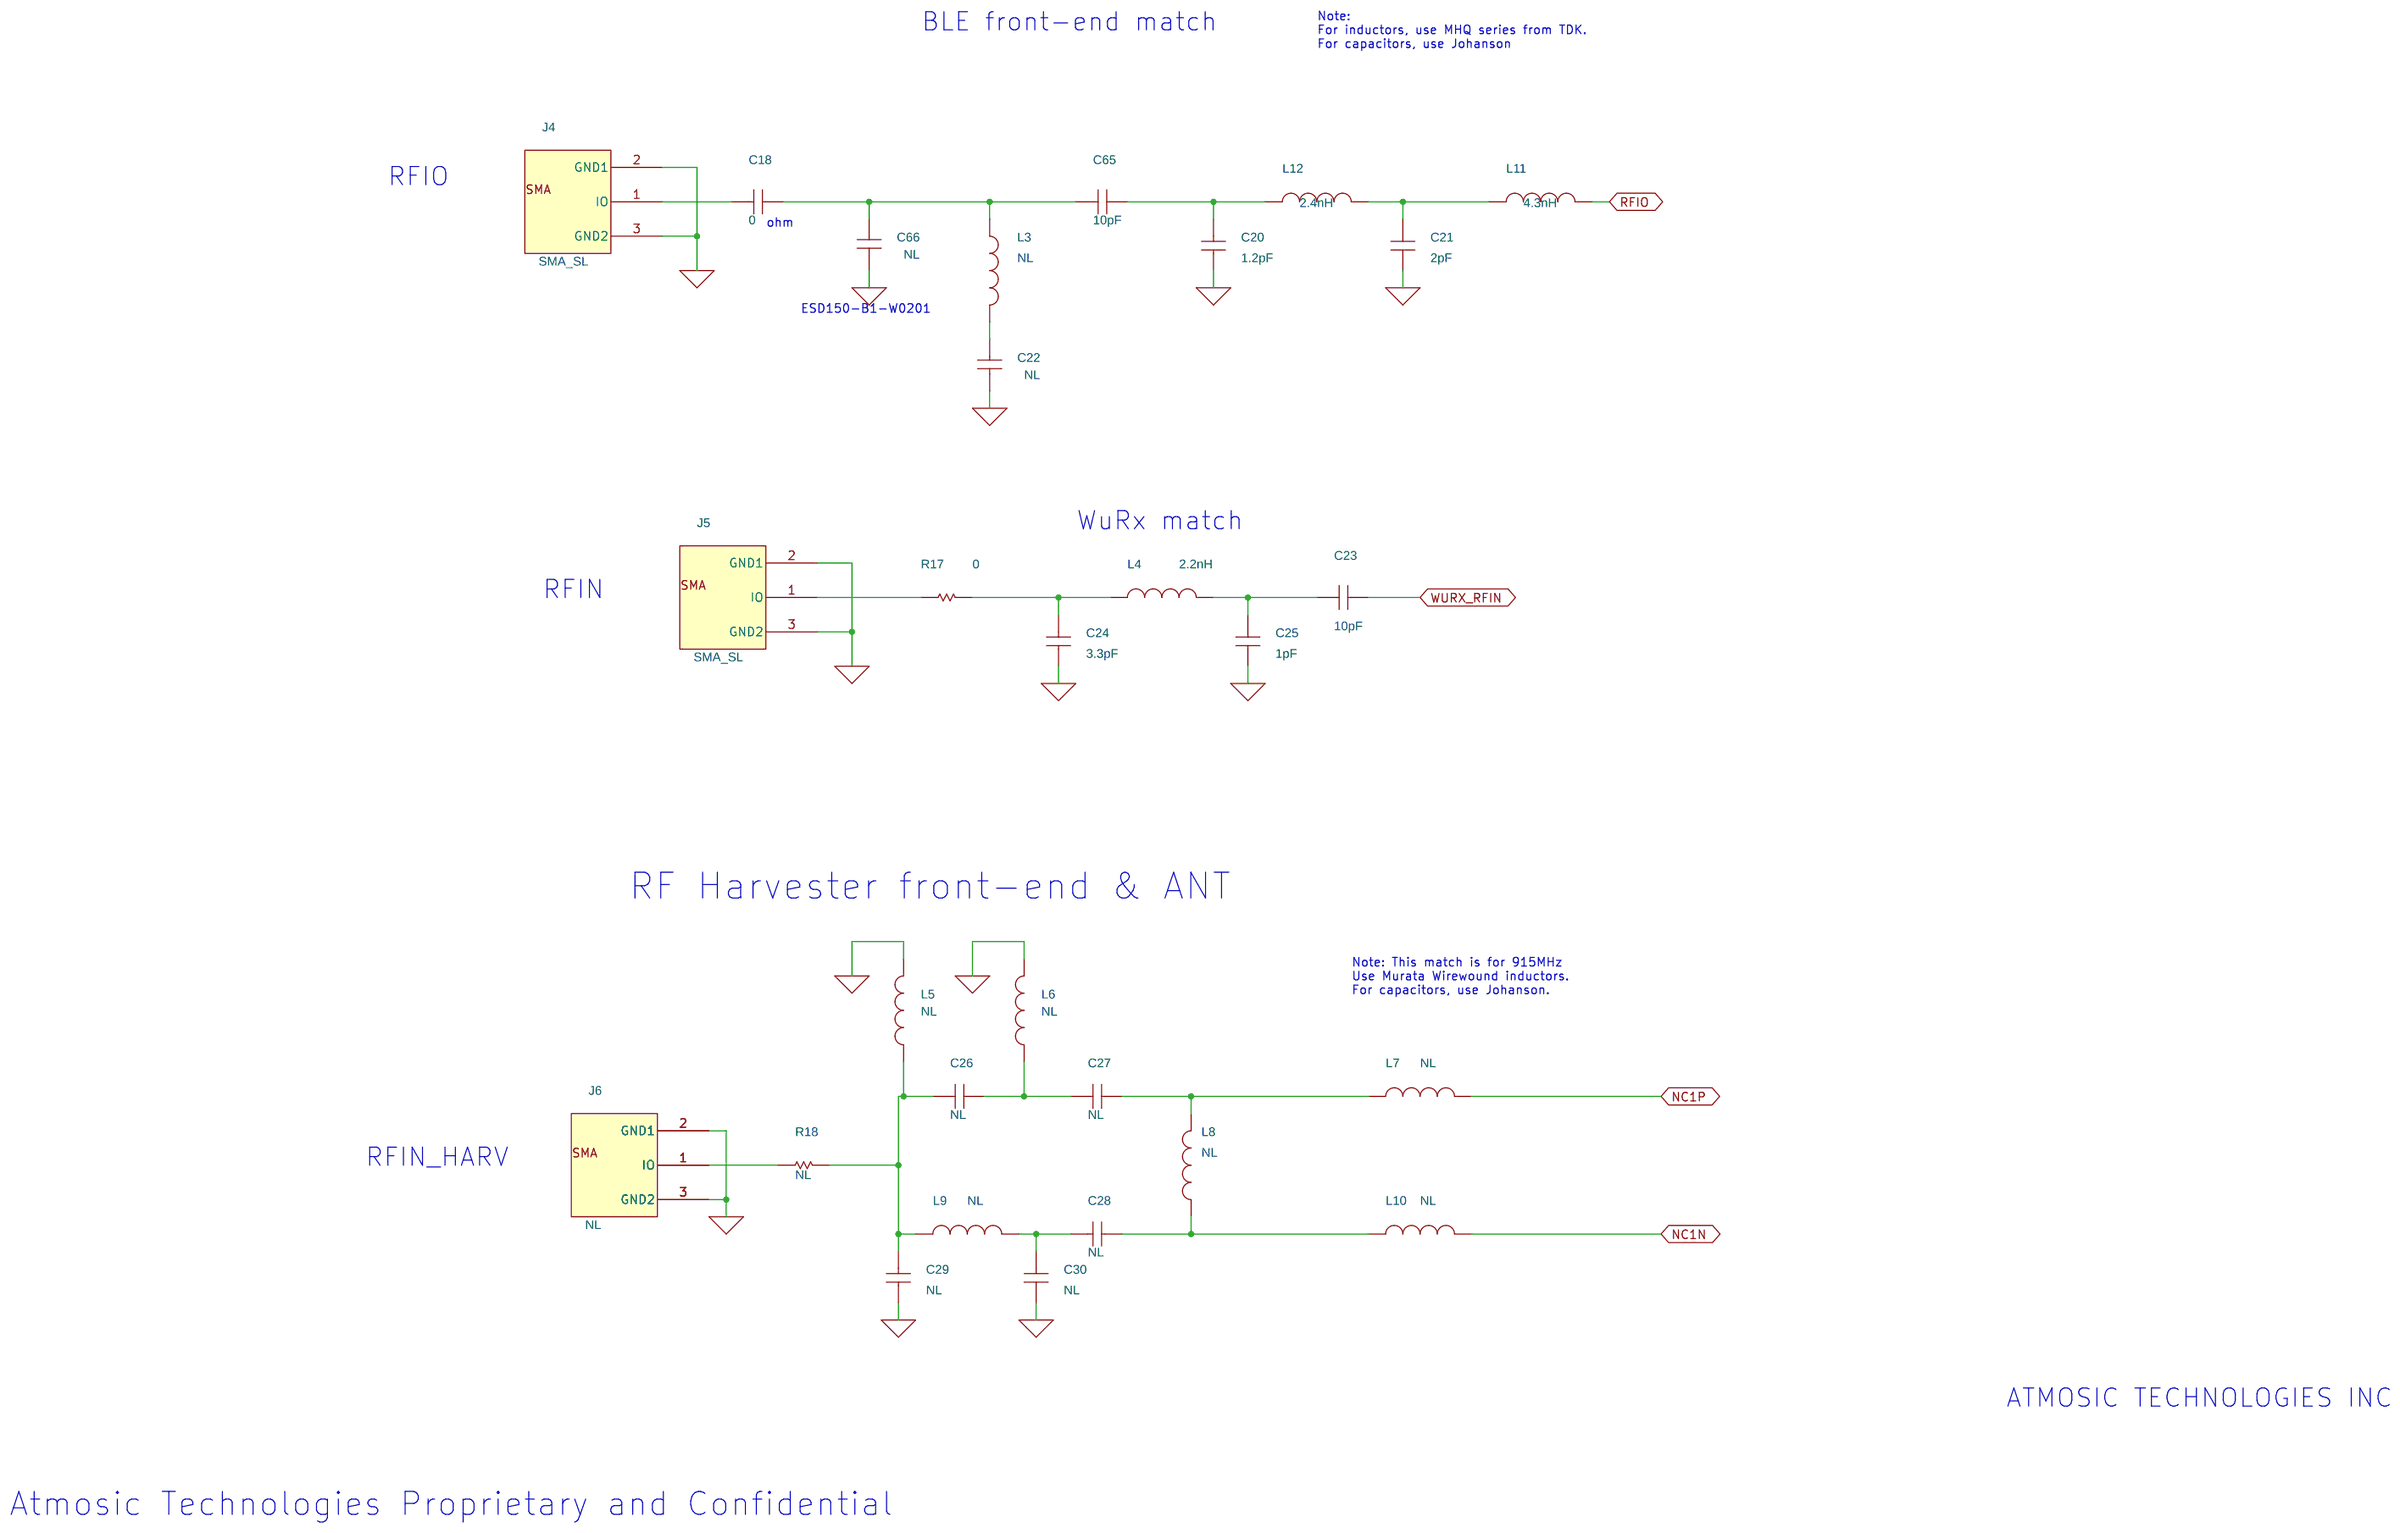
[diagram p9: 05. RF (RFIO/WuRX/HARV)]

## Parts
sheet 03. ATM3330
C1  1uF  [0402]
C2  10uF  [0402]
C3  10uF  [0402]
C4  10uF  [0402]
C5  10uF  [0402]
C6  10uF  [0402]
C7  10uF  [0402]
C8  NL  [1206]
C10  1uF  [0402]
C11  1uF  [0402]
C12  10uF  [0603]
C13  NL  [0603]
C14  0  [0402]
C17  1uF  [0402]
C64  1uF  [0402]
C68  NL  [0402]
C69  NL  [0603]
C70  NL  [0603]
C71  NL  [0402]
C73  NL  [0402]
D1  NL  [TRA-SOT23]
J3  HEADER 3  [HDR1X3]
J19  NL  [CONN-OSTVN02A150]
J26  HEADER 3  [HDR1X3]
JP1  NL  [HDR1X2]
JP5  NL  [HDR1X2]
JP26  JUMPER-2  [HDR1X2]
JP28  NL  [HDR1X2]
L1  3.3uH  [IND-2016-2]
Q4  NL  [TRA-SOT23]
R6  1  [0402]
R7  NL  [0402]
R8  1M  [0402]
R13  0  [0402]
R15  100K  [0402]
R101  NL  [0402]
R102  NL  [0402]
R103  0  [0402]
R105  NL  [0603]
R106  NL  [0603]
R107  NL  [0402]
S1  SW-TACT-4P  [SWI-SM-PTS645]
SB2  Short  [SB]
SB6  Open  [SB]
SB9  Short  [SB]
SB145  Short  [SB]
SB146  Short  [SB]
TP1  NL  [TESTPIN]
TP3  TP-BLK  [TESTPIN]
TP4  TP-BLK  [TESTPIN]
TP5  TP-BLK  [TESTPIN]
TP23  TP-BLK  [TESTPIN]
TP25  TP-WHT  [TESTPIN]
U1  ATM3330  [QFN-56-7X7-0.4MM-EP5.2MM]
Y1  32K XTAL  [XTAL-SMD2-3.2X1.5MM]
Y2  K301F  [XTAL-ECX-2236]
sheet 04. GPIO Mapping
C56  0.1uF  [0402]
C57  0.1uF  [0402]
C58  0.1uF  [0402]
C59  0.1uF  [0402]
C60  0.1uF  [0402]
C72  0.1uF  [0402]
JP8  JUMPER-2  [HDR1X2]
JP11  JUMPER-2  [HDR1X2]
JP25  JUMPER-2  [HDR1X2]
JP27  JUMPER-2  [HDR1X2]
R72  1M  [0402]
R74  1M  [0402]
R79  1M  [0402]
R98  1M  [0402]
R99  1M  [0402]
R100  0  [0402]
SB131  Short  [SB]
SB143  Short  [SB]
TP24  TP  [TESTPAD50]
U7  NX3DV2567  [XQFN16]
U9  NX3DV2567  [XQFN16]
U10  NX3DV2567  [XQFN16]
U11  NX3DV2567  [XQFN16]
U12  NX3DV2567  [XQFN16]
U16  NX3DV2567  [XQFN16]
sheet 05. RF (RFIO/WuRX/HARV)
C18  0  [0402]
C20  1.2pF  [0402]
C21  2pF  [0402]
C22  NL  [0402]
C23  10pF  [0402]
C24  3.3pF  [0402]
C25  1pF  [0402]
C26  NL  [0402]
C27  NL  [0402]
C28  NL  [0402]
C29  NL  [0402]
C30  NL  [0402]
C65  10pF  [0402]
C66  NL  [0201]
J4  SMA_SL  [SMA-RA]
J5  SMA_SL  [SMA-RA]
J6  NL  [SMA-RA]
L3  NL  [0402]
L4  2.2nH  [0402]
L5  NL  [0402]
L6  NL  [0402]
L7  NL  [0402]
L8  NL  [0402]
L9  NL  [0402]
L10  NL  [0402]
L11  4.3nH  [0402]
L12  2.4nH  [0402]
R17  0  [0402]
R18  NL  [0402]
sheet 06. Buttons LEDs Sensors
C31  0.1uF  [0402]
C32  0.1uF  [0402]
C62  NL  [0402]
C67  1uF  [0402]
DS1  RED LED  [LED-0603]
DS2  YELLOW LED  [LED-0603]
DS3  BLUE LED  [LED-0603]
Q2  MMBT3904/SOT  [TRA-SOT23]
Q3  MMBT3904/SOT  [TRA-SOT23]
R19  1K  [0402]
R20  0  [0402]
R22  0  [0402]
R23  10K  [0402]
R24  100K  [0402]
R25  NL  [0402]
R26  560  [0402]
R27  1K  [0402]
R28  470  [0402]
R29  1M  [0402]
R30  1K  [0402]
R31  1M  [0402]
R32  NL  [0402]
R69  10K  [0402]
R71  NL  [0402]
R84  NL  [0402]
R85  NL  [0402]
R95  1M  [0402]
R96  1M  [0402]
R97  NL  [0402]
S2  SW-TACT-4P  [SWI-SM-PTS645]
S3  SW-TACT-4P  [SWI-SM-PTS645]
SW1  NL  [SW-DIP-219-3]
U3  LIS3DH  [LGA-16-3X3]
U4  ENS210-LQFM  [SON-04-2X2MM]
U13  MX25R4035FZUIL0  [USON-8-2X3-EP]
U15  NL  [SOT23-6]
sheet 07. Connectors
C35  NL  [0402]
C36  NL  [0402]
C37  NL  [0402]
C38  NL  [0402]
C39  NL  [0402]
C40  NL  [0402]
J12  HEADER 25X2  [HDR25X2]
sheet 08. MK22
C41  0.1uF  [0402]
C42  0.1uF  [0402]
C43  0.1uF  [0402]
C44  0.1uF  [0402]
C45  0.1uF  [0402]
C46  NL  [0402]
DS4  GREEN LED  [LED-0603]
J15  FCI 10118194-0001LF  [10118194-0001LF]
J27  NL  [MOLEX-105133-0031]
R38  0  [0402]
R39  0  [0402]
R40  NL  [0402]
R41  0  [0402]
R42  0  [0402]
R43  0  [0402]
R45  10K  [0402]
R46  33  [0402]
R47  33  [0402]
R48  0  [0402]
R49  0  [0402]
R50  0  [0402]
R51  0  [0402]
R66  1K  [0402]
R67  10k  [0402]
R83  10k  [0402]
TC1  TC2030-IDC  [CON-TC2030-IDC]
TP6  TP  [TESTPAD50]
TP7  TP  [TESTPAD50]
TP8  TP  [TESTPAD50]
TP9  TP  [TESTPAD50]
TP10  TP  [TESTPAD50]
TP11  TP  [TESTPAD50]
TP13  TP  [TESTPAD50]
TP14  TP  [TESTPAD50]
TP15  TP  [TESTPAD50]
TP16  TP  [TESTPAD50]
U5  NSP4201MR6  [TSOP-6]
U6  MK22FN128VLH10  [LQFP-64-10X10-0.5MM]
sheet 09. Power
BT2  NL  [BAT-HOLDER-2032]
C47  NL  [0402]
C48  1uF  [0402]
C49  1uF  [0402]
C50  1nF  [0402]
C51  1uF  [0402]
C52  1uF  [0402]
C53  NL  [0402]
C54  1uF  [0402]
C55  1uF  [0402]
C61  0.01uF  [0402]
FD1  TEST POINT  [FID-G]
FD2  TEST POINT  [FID-G]
FD3  TEST POINT  [FID-G]
FD4  TEST POINT  [FID-G]
J21  HEADER 3  [HDR1X3]
J22  HEADER 3  [HDR1X3]
J23  HEADER 3  [HDR1X3]
J25  OSTVN02A150  [CONN-OSTVN02A150]
J28  HEADER 3  [HDR1X3]
JP12  NL  [HDR1X2]
JP13  NL  [HDR1X2]
JP14  NL  [HDR1X2]
JP15  NL  [HDR1X2]
JP16  NL  [HDR1X2]
JP24  NL  [HDR1X2]
MT1  TEST POINT  [HOLE-250R125]
MT2  TEST POINT  [HOLE-250R125]
MT3  TEST POINT  [HOLE-250R125]
MT4  TEST POINT  [HOLE-250R125]
R53  0  [0402]
R54  NL  [0402]
R57  0  [0402]
R58  27K 1%  [0402]
R59  10K 1%  [0402]
R60  0  [0402]
R61  NL  [0402]
R62  NL  [0402]
R73  0  [0402]
R77  0  [0402]
R78  0  [0402]
R104  NL  [0402]
SB136  Short  [SB]
SB137  Short  [SB]
SB138  Short  [SB]
SB140  Short  [SB]
SB141  Short  [SB]
SB142  Open  [SB]
SB147  Short  [SB]
TP19  TP-WHT  [TESTPIN]
TP20  TP-WHT  [TESTPIN]
TP21  TP-WHT  [TESTPIN]
TP22  TP-WHT  [TESTPIN]
VR1  MIC5255-3.3YD5  [SOT23-5]
VR2  AP2127K-ADJTRG1  [SOT23-5]
VR3  AP2127K-1.8TRG1  [SOT23-5]

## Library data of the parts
C1-C8 C10-C14 C17 C18 C20-C32 C35-C62 C64-C73 = SMALL_CAP
D1 = DIODE_1A2C3COM
J3 J21-J23 J26 J28 = HEADER_3
J19 J25 = CON2
JP1 JP5 JP8 JP11-JP16 JP24-JP28 = JUMPER-2
L1 L3-L12 = INDUCTOR
Q4 = 2N7000_0
R6-R8 R13 R15 R17-R20 R22-R32 R38-R43 R45-R51 R53 R54 R57-R62 R66 R67 R69 R71-R74 R77-R79 R83-R85 R95-R107 = SMALL_R1
S1-S3 = SW-TACT-4P-5
SB2 SB6 SB9 SB131 SB136-SB138 SB140-SB143 SB145-SB147 = SB
TP1 TP3-TP5 TP19-TP23 TP25 = TP
U1 = ATM3332-202_2
Y1 = XTAL
Y2 = XTAL-OSC-4P_0
TP6-TP11 TP13-TP16 TP24 = TP_0
U7 U9-U12 U16 = NX3DV2567
J4-J6 = SMA_SL
DS1-DS4 = LED
Q2 Q3 = MMBT3904_SOT
SW1 = SW_DIP-3
U3 = LIS3DHTR_0
U4 = ENS210-LQFM_2
U13 = LM258DRG3_0
U15 = 24AA014_0
J12 = HEADER_25X2
J15 = USB_CONN_1_v2
J27 = USB_CONN_1
TC1 = TC2030-IDC
U5 = NSP4201MR6_0
U6 = MK22FN128VLH10_0
BT2 = BAT
FD1-FD4 MT1-MT4 = TEST_POINT
VR1-VR3 = VAR_REG

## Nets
1.8V: J22.3 R60.2
3.0V: J21.1 J22.1 R57.2
3.3V: C39.2 C40.1 C45.1 J12.26 R26.2 R28.2 R53.2 U6.7(USBVDD)
AVDD1: C12.1 C13.1 R6.1 U1.1(AVDD1)
AVDD1P: C4.1 JP5.1 SB9.1 U1.25(AVDD1P)
AVDDPA: J3.2 R13.1
DVDD1: C1.1 JP1.2 SB2.2 U1.30(DVDD1)
DVDD1P: C3.1 JP1.1 SB2.1 U1.27(DVDD1P)
GND_SIGNAL: BT2.2(NEG) C1.2 C2.2 C3.2 C4.2 C5.2 C6.2 C7.2 C8.1 C10.2 C11.2 C12.2 C13.2 C14.2 C17.2 C20.1 C21.1 C22.2 C24.1 C25.1 C29.1 C30.1 C31.2 C32.2 C35.1 C36.2 C37.1 C38.2 C39.1 C40.2 C41.2 C42.2 C43.2 C44.2 C45.2 C46.2 C48.1 C49.1 C51.1 C52.1 C54.1 C55.1 C56.2 C57.2 C58.2 C59.2 C60.2 C61.1 C62.2 C64.2 C66.2 C67.1 C68.2 C69.1 C70.1 C72.2 C73.1 DS1.1(CATHODE) J4.2(GND1) J4.3(GND2) J5.2(GND1) J5.3(GND2) J6.2(GND1) J6.3(GND2) J12.1 J12.27 J15.5(GND) J15.S1(CASE) J15.S2(CASE) J15.S3(CASE) J15.S4(CASE) J15.S5(CASE) J15.S6(CASE) J25.2 J27.5(GND) J27.S1(CASE) J27.S2(CASE) J27.S3(CASE) L5.2 L6.2 MT1.1 MT2.1 MT3.1 MT4.1 Q2.2(E) Q3.2(E) Q4.2(SOURCE) R8.1 R15.1 R25.1 R29.1 R32.1 R45.1 R59.2 R62.2 R72.1 R74.1 R79.1 R98.1 R99.1 R103.2 R106.1 S3.3 S3.4 SB6.2 SB146.2 TC1.5(GND) TP3.1(TP) TP4.1(TP) TP5.1(TP) TP23.1(TP) U1.57(EGND) U3.5(GND) U3.10(RES) U3.12(GND_1) U4.4(VSS) U4.5(VSS_1) U5.2(GND) U6.4(VSS) U6.15(VREFL) U6.16(VSSA) U6.31(VSS) U6.32(PTA18) U6.33(PTA19) U6.47(VSS) U7.6(GND) U9.6(GND) U10.6(GND) U11.6(GND) U12.6(GND) U13.4(GND) U13.9(EP) U15.2(VSS) U15.4(A1) U16.6(GND) VR1.2(GND) VR2.2(GND) VR3.2(GND) Y2.2(NC) Y2.4(NC)
VBAT: C7.1 J23.1 J26.1 J28.3 U1.20(VBAT)
VBATLI: C64.1 R105.2 SB147.1 U1.28(VBATLI)
VCC_BIDS: C62.1 R20.2 R22.2 R23.1 R24.1 R31.2 R69.2 R71.2 R84.2 R85.2 R97.2 S2.3 S2.4 U10.15(1Y1) U15.6(VCC)
VCC_F: C67.2 R95.1 R96.1 U11.15(1Y1) U13.8(VCC)
VCC_USB: C49.2 C52.2 C55.2 DS4.2(ANODE) J15.1(VBUS) J27.1(VBUS) SB142.2 TP21.1(TP) U5.5(VP) VR1.1(VIN) VR1.3(EN) VR2.1(VIN) VR2.3(EN) VR3.1(VIN) VR3.3(EN)
VCCIO: C35.2 C36.1 C37.2 C38.1 C56.1 C57.1 C58.1 C59.1 C60.1 C72.1 J12.2 J12.50 J26.3 JP8.1 JP11.1 JP25.1 JP27.1 R78.2 R104.2 U7.14(VCC) U9.14(VCC) U10.14(VCC) U11.14(VCC) U12.14(VCC) U16.14(VCC)
VCCIO_K22: C41.1 C42.1 C43.1 C44.1 JP14.1 SB138.1 TC1.1(VCC) U6.3(VDD) U6.13(VDDA) U6.14(VREFH) U6.21(VBAT) U6.26(PTA4/LLWU_P3) U6.30(VDD) U6.48(VDD)
VDDIO: C10.1 C11.1 JP13.1 JP24.1 SB137.1 U1.8(VDDIO) U1.39(VDDIO)
VDDIO_FLASH: JP16.1 SB141.1 U11.16(1Z)
VDDIO_SENS: JP15.1 SB140.1 U10.16(1Z)
VDDIOP: C6.1 J3.1 J23.3 JP26.2 U1.24(VDDIOP)
BBOOT: R40.1 R66.1 U9.1(1Y0)
BUTTON_1: R29.2 S2.1 S2.2 SB131.2
BUTTON_2: R31.1 S3.1 S3.2 U16.15(1Y1)
DM: R46.1 U6.6(USB0_DM)
DP: R47.1 U6.5(USB0_DP)
FLASH_CS_L: R95.2 U11.7(3Y1) U13.1(CS#)
FLASH_RESET_L: R96.2 U11.3(2Y1) U13.7(RESET#)
FLASH_SCLK: U11.11(4Y1) U13.6(SCLK)
FLASH_SIO0: U12.3(2Y1) U13.5(SI/SIO0)
FLASH_SIO1: U12.7(3Y1) U13.2(SO/SIO1)
FLASH_SIO2: U12.11(4Y1) U13.3(WP#/SIO2)
G_INT: U3.11(INT1) U10.11(4Y1)
I2C1_SCK: R71.1 R97.1 U3.4(SCL/SPC) U4.2(SCL) U10.7(3Y1) U15.1(SCL)
I2C1_SDA: R69.1 R84.1 U3.6(SDA/SDI/SDO) U4.3(SDA) U10.3(2Y1) U15.3(SDA)
LED_1: R19.2 U16.3(2Y1)
LED_2: R27.1 U16.7(3Y1)
LED_3: R30.1 U16.11(4Y1)
LiOn_Bat: C70.2 D1.2(K) J25.1 J28.1
MODE_0: J12.3 SW1.4(B3) U1.34(P11)
MODE_1: J12.6 SW1.5(B2) U1.37(P14)
MODE_2: J12.16 SW1.6(B1) U1.48(P24)
NC1N: L10.2 U1.18(NC)
NC1P: L7.2 U1.17(NC)
NO_K22: JP11.2 R74.2 R83.1 SB143.1 U7.2(S)
P0: J12.32 U1.5(P0) U9.4(2Z)
P1: J12.33 U1.6(P1) U9.8(3Z)
P2: J12.34 U1.7(P2)
P3: C73.2 J12.35 R105.1 R106.2 U1.9(P3)
P4: J12.36 SB145.2 U1.10(P4)
P5: J12.37 SB131.1 U1.11(P5)
P6: J12.38 U1.12(P6) U10.8(3Z)
P7: J12.39 U1.13(P7) U10.4(2Z)
P8: J12.40 U1.14(P8) U16.16(1Z)
P9: J12.41 U1.15(P9) U16.8(3Z)
P10: J12.42 U1.33(P10) U16.12(4Z)
P12: J12.4 U1.35(P12) U7.12(4Z)
P13: J12.5 R100.2 U1.36(P13)
P15: J12.7 U1.38(P15) U7.4(2Z)
P16: J12.8 U1.40(P16)
P17: J12.9 U1.41(P17)
P18: J12.10 U1.42(P18) U11.12(4Z)
P19: J12.11 U1.43(P19) U11.8(3Z)
P20: J12.12 U1.44(P20) U12.4(2Z)
P21: J12.13 U1.45(P21) U12.8(3Z)
P22: J12.14 U1.46(P22) U12.12(4Z)
P23: J12.15 U1.47(P23) U11.4(2Z)
P25: J12.17 R15.2 U1.49(P25) U9.16(1Z)
P26: J12.21 U1.52(P26) U10.12(4Z)
P27: J12.22 U1.53(P27) U9.12(4Z)
P28: J12.23 JP28.1 R107.1 U1.54(P28)
P29: J12.24 U1.55(P29) U16.4(2Z)
P30: J12.25 U1.56(P30) U7.8(3Z)
PWD: J12.49 R8.2 R67.1 S1.1 S1.2 U1.16(PWD)
RES1: C14.1 R7.2 U1.19(RES)
RES2: R103.1 SB142.1 U1.29(RES)
RFIO: L11.2 U1.2(RFIO)
SWDCLK_K22: R39.1 U9.5(2Y0)
SWDIO_K22: R38.1 U9.9(3Y0)
UART0_CTS_K22: R51.1 U7.13(4Y0)
UART0_RTS_K22: R50.1 U7.1(1Y0)
UART0_RX_K22: R48.1 U7.9(3Y0)
UART0_TX_K22: R49.1 U7.5(2Y0)
UART1_CTS_K22: R43.1 TP7.1(TP)
UART1_RTS_K22: R42.1 TP6.1(TP)
UART1_TX_K22: R41.1 U9.13(4Y0)
UART2_CTS_K22: TP11.1(TP) U6.44(PTC1/LLWU_P6)
UART2_RTS_K22: TP10.1(TP) U6.45(PTC2)
UART2_RX_K22: TP8.1(TP) U6.49(PTC4/LLWU_P8)
UART2_TX_K22: TP9.1(TP) U6.46(PTC3/LLWU_P7)
USB_D+: J15.3(D+) J27.3(D+) R47.2 U5.3(IO2) U5.4(IO3)
USB_D-: J15.2(D-) J27.2(D-) R46.2 U5.1(IO1) U5.6(IO4)
USE_FLASH: JP8.2 R79.2 U11.2(S) U12.2(S)
VAUX: C5.1 JP26.1 U1.26(VAUX)
VCOINCELL: BT2.1(POS) J21.3 R104.1
VHARV: J19.1 R102.2
VSTORE: C2.1 C8.2 C68.1 J3.3 R101.2 R107.2 TP25.1(TP) U1.22(VSTORE)
WURX_RFIN: C23.1 U1.3(WURX_RFIN)
XTALI_16M: U1.51(XTALO_16M) Y2.1(HOT)
XTALI_32K: SB6.1 U1.32(XTALI_32K) Y1.2
XTALO_16M: U1.50(XTALI_16M) Y2.3(HOT)
XTALO_32K: U1.31(XTALO_32K) Y1.1
N16735640: JP5.2 R6.2 SB9.2
N16846913: R7.1 TP1.1(TP)
N16873328: L1.1 U1.21(LEXT1)
N16873338: L1.2 U1.23(LEXT2)
N16893506: C17.1 R13.2 U1.4(AVDDPA)
N17095028: C47.2 C48.2 R53.1 R54.1 VR1.5(VOUT)
N17095050: C47.1 C61.2 R54.2 VR1.4(ADJ)
N17095106: J21.2 JP12.2 R73.1 SB136.2
N17095108: J23.2 JP13.2 JP15.2 JP16.2 R77.2 SB137.2 SB140.2 SB141.2
N17095279: C53.2 C54.2 R60.1 R61.1 VR3.5(VOUT)
N17095319: C53.1 R61.2 R62.1 VR3.4(ADJ)
N17095349: J28.2 JP12.1 SB136.1 SB147.2
N17095531: C50.2 C51.2 R57.1 R58.1 VR2.5(VOUT)
N17095557: C50.1 R58.2 R59.1 VR2.4(ADJ)
N17096185: J22.2 JP14.2 JP24.2 R78.1 SB138.2 TP20.1(TP)
N17100046: R99.2 SB143.2 TP24.1(TP) U9.2(S)
N17100334: JP25.2 R72.2 U10.2(S)
N17101171: C18.2 J4.1(IO)
N17101173: C18.1 C65.2 C66.1 L3.1
N17101183: C20.2 C65.1 L12.1
N17101189: C21.2 L11.1 L12.2
N17101247: C22.1 L3.2
N17101303: J5.1(IO) R17.2
N17101305: C24.2 L4.1 R17.1
N17101311: C23.2 C25.2 L4.2
N17101384: C26.2 C29.2 L5.1 L9.1 R18.2
N17101386: C26.1 C27.2 L6.1
N17101427: C27.1 L7.1 L8.2
N17101464: J6.1(IO) R18.1
N17101492: C28.1 L8.1 L10.1
N17101511: C28.2 C30.2 L9.2
N17102737: DS1.2(ANODE) R19.1
N17102803: C31.1 R20.1 U3.1(VDD_IO) U3.14(Vdd)
N17102805: C32.1 R22.1 U4.1(VDD)
N17102917: DS2.2(ANODE) R26.1
N17102919: DS2.1(CATHODE) Q2.3(C)
N17103005: R23.2 R25.2 U3.7(SDO/SA0)
N17103017: Q2.1(B) R27.2
N17103021: R24.2 U3.8(CS)
N17103073: DS3.2(ANODE) R28.1
N17103075: DS3.1(CATHODE) Q3.3(C)
N17103123: Q3.1(B) R30.2
N17103301: R32.2 SW1.1(A1) SW1.2(A2) SW1.3(A3)
N17103574: R85.1 U15.5(A0)
N17105483: R67.2 U6.2(PTE1/LLWU_P0)
N17105496: R83.2 TP15.1(TP) U6.58(PTD1)
N17105530: R38.2 U6.63(PTD6/LLWU_P15)
N17105555: R39.2 U6.62(PTD5)
N17105589: R66.2 U6.61(PTD4/LLWU_P14)
N17105614: R40.2 U6.60(PTD3)
N17105656: R41.2 U6.59(PTD2/LLWU_P13)
N17105670: R42.2 U6.54(PTC9)
N17105708: R43.2 U6.53(PTC8)
N17105834: DS4.1(CATHODE) R45.2
N17106014: R48.2 U6.40(PTB17)
N17106031: R49.2 U6.39(PTB16)
N17106052: R50.2 U6.38(PTB3)
N17106071: R51.2 U6.37(PTB2)
N17106085: C46.1 TC1.3(NRESET) U6.34(RESET_B)
N17106116: TC1.4(SWCLK) U6.22(PTA0)
N17106118: TC1.6(SWO) U6.24(PTA2)
N17106120: TC1.2(SWDIO) U6.25(PTA3)
N17109315: C69.2 D1.1(A) R101.1 R102.1
N17109363: C71.2 D1.3(C)
N17109373: C71.1 SB145.1
N17109503: J19.2 Q4.3(DRAIN) SB146.1
N17109714: J26.2 S1.3 S1.4
N17112014: JP28.2 Q4.1(GATE)
N17114657: JP27.2 R98.2 U16.2(S)
N17157106: R100.1 U7.16(1Z)
N17180267: R77.1 TP19.1(TP)
N17180268: R73.2 TP22.1(TP)
N17180470: TP16.1(TP) U6.64(PTD7)
N17180471: TP13.1(TP) U6.56(PTC11/LLWU_P11)
N17180472: TP14.1(TP) U6.57(PTC0/LLWU_P12)

Not connected (* = marked no-connect by the designer): FD1 1*; FD2 1*; FD3 1*; FD4 1*; J12 18 19* 20* 28* 29* 30* 31* 43* 44* 45* 46* 47* 48*; J15 4(IO)*; J27 4(IO)*; U3 2(NC)* 3(NC_1)* 9(INT2)* 13(ADC3)* 15(ADC2)* 16(ADC1)*; U6 1(PTE0/CLKOUT32K)* 8(NC)* 9(ADC0_DP0/ADC1_DP3)* 10(ADC0_DM0/ADC1_DM3)* 11(ADC1_DP0/ADC0_DP3)* 12(ADC1_DM0/ADC0_DM3)* 17(VREF_OUT)* 18(DAC0_OUT)* 19(XTAL32)* 20(EXTAL32)* 23(PTA1)* 27(PTA5)* 28(PTA12)* 29(PTA13/LLWU_P4)* 35(PTB0/LLWU_P5)* 36(PTB1)* 41(PTB18)* 42(PTB19)* 43(PTC0)* 50(PTC5/LLWU_P9)* 51(PTC6/LLWU_P10)* 52(PTC7)* 55(PTC10)*; U7 3(2Y1)* 7(3Y1)* 10(N_C_)* 11(4Y1)* 15(1Y1)*; U9 3(2Y1)* 7(3Y1)* 10(N_C_)* 11(4Y1)* 15(1Y1)*; U10 1(1Y0)* 5(2Y0)* 9(3Y0)* 10(N_C_)* 13(4Y0)*; U11 1(1Y0)* 5(2Y0)* 9(3Y0)* 10(N_C_)* 13(4Y0)*; U12 1(1Y0)* 5(2Y0)* 9(3Y0)* 10(N_C_)* 13(4Y0)* 15(1Y1)* 16(1Z)*; U16 1(1Y0)* 5(2Y0)* 9(3Y0)* 10(N_C_)* 13(4Y0)*

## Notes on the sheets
sheet 1
- Common EVB Operation Modes
- ATMOSIC TECHNOLOGIES INC
sheet 2
- ATM3330 EVALUATION BOARD (with J-Link OB)
- Release Date
- Revision
- Design Eng.
- Design Notes
- 10/03/21
- -00
- AD
- Initial release
- 12/01/21
- -10
- AD
- Ground pin 33 of MK22
  Change Paris Part Number to ATM3330e
  Change resistors and supplies to adjust brightness of LEDs
  Change R61 to 20K and R62 to 16K due to availability
  Change several components to NL by default
  Short SB119 by default
  Add two SB121 and SB122 to VDDPA
- 5/25/22
- -20
- AD
- Remove the 20-pin Interface connector J8
  Remove the Arduino connectors J10, J11, J13, J14
  Remove the Trace/Debug connectors J7, J9
  All GPIOS directly connected to J12
  Analog switches are used to connect/disconnect K22 and peripherals
- 7/29/22
- -21
- AD
- Loaded R69 I2C data pull-up
  Updated RFIO Match
  Updated Li-Ion charge pump ckt
  Changed VAUX cap to 4.7uF
  Change Harvester match to NL
- Updated U1 pin names for pins 20 (VBAT) and 28 (VBATLI)
  Renamed nets: VBATT to VBAT, and VBATTLI to VBATLI
  Updated RFIO Match (L11, C21, L12, C20)
  Updated WuRx Match (C25, L4, C24)
- 11/08/22
- -22
- AD
- Changed JP29 to J28 to select between VBAT and VBATLI
  Removed C9 and JP3 (harvesting meter), added a TP25 (VSTORE)
  Added R99 to keep SWD and BBOOT connected by default
  Added short SB145 and R101, R102 to Li-Ion Charging Ckt
  Added short SB146 to ground the negative terminal of PV cell
  Changed C63 (0ohms on RES pin 29 of U1) to R103 (0ohms)
  Added R104 as an option to connect VCCIO to Coin Cell
  Added Brownout/LPComp Ckt (R105, R106, C73)
  Added R100 between P13 and U7
  Changed 32kHz clock for boost ckt from P13 to P4
- 11/21/22
- -31
- AD
- 03/31/23
- -32
- AD
- Modified the description for C12
- 11/03/25
- -33
- AD
- Changed C5 (VAUX) and C6 (VDDIOP) to 10uF
- ATMOSIC TECHNOLOGIES INC
- Atmosic Technologies, Inc
- 2130 Gold Street, Suite 200
  San Jose, CA 95002
- Atmosic Technologies Proprietary and Confidential
sheet 3
- Page 1 - Revision notes
  Page 2 - Block diagram
  Page 3 - ATM3330e, decoupling, Li-Ion charging ckt
  Page 4 - GPIO Mapping, Analog switches
  Page 5 - RF matching circuits
  Page 6 - Sensors, Flash, LEDs, Buttons
  Page 7 - 50-pin Connector
  Page 8 - MK22 Controller
  Page 9 - Power supplies and configurations
  Page 10 - Jumper settings for common Operation Modes
- Block Diagram
- Li-Ion Bat
  Connector
- Ext Supply
  Connectors
- USB
  Conn
- On-board Power Supplies
- LEDs
- Buttons
- Sensors
- Programming
  Pads
- MK22
- 50-pin
  Connector
- Analog
  Switches
- ATM3330
- Wake-up Rx
  Match
- SMA Conn
- Flash
- GPIOs: P0 - P30
- BLE Tx/Rx
  Match
- SMA Conn
- Reset Button
- ATMOSIC TECHNOLOGIES INC
sheet 4
- Change C12 to 22uF if needs
  to operate below -10°C
- 16MHz XTAL
- Li-Ion Charging Ckt
- PV Cell connector
- J19 - PCB Block Terminal Connector
  PV cell wires connect to the PCB here
- Power down switch
- PTS645 SMD
- Benign boot
- 7X7 QFN
- ATMOSIC TECHNOLOGIES INC
- Atmosic Technologies Proprietary and Confidential
sheet 5
- GPIO MUX
- CONNECT SENSORS TO ATM3330
- ISOLATE MK22 FROM ATM3330
- CONNECT FLASH TO ATM3330
- Install to
  connect Sensors
- Install to
  isolate MK22
- Install to
  connect Flash
- CONNECT LEDS/BUTTONS TO ATM3330
- Assert to
  isolate MK22
- Install to
  connect LEDs
  and Buttons
- ATMOSIC TECHNOLOGIES INC
- Atmosic Technologies Proprietary and Confidential
sheet 6
- MOTION SENSOR
- LEDS
- HARV MODES
- BIDS (1Kbits)
- SA0: I2C less significant bit of the device address.
  High: 0x19
  Default: input with internal pull-up
- The I2C slave device address: 0x51
- TEMP/HUM SENSOR
- 24AA014
- PUSH BUTTONS
- The I2C slave device address of ENS210: 0x43
- FLASH
- PTS645 SMD
- PTS645 SMD
- USON 2x3mm
- ATMOSIC TECHNOLOGIES INC
sheet 7
- SENSOR HUB 50-PIN CONNECTOR
- ATMOSIC TECHNOLOGIES INC
sheet 8
- USB ESD
- (Benign Boot)
- 90 OHM DIFF PAIR
- USB
- USB OPTION
- MOLEX-105133-031
- J-Link OB
  Programming Pads
- ATMOSIC TECHNOLOGIES INC
sheet 9
- VCC_USB
- Supply for MK22 USB
- VBAT/LI
- VDDIO
- On-Board Voltage Regulators
- For current
  measurements
- Supply for VCCIO
- BAT 2032
- Supply for VBAT
  and/or VCCIO
- For current
  measurements
- J25 - PCB Block Terminal Connector
  Li-Ion Battery wires connect to the PCB here
- Jumper on pins 1-2 for
  external Li-Ion through VBATLI
  Jumper on pins 2-3 to connect
  VBAT to VBATLI for VBAT operation
- VCCIO
- MOUNTING HOLES
- BOARD FIDUCIALS
- ATMOSIC TECHNOLOGIES INC
sheet 10
- BLE front-end match
- Note:
  For inductors, use MHQ series from TDK.
  For capacitors, use Johanson
- RFIO
- ohm
- ESD150-B1-W0201
- WuRx match
- RFIN
- RF Harvester front-end & ANT
- Note: This match is for 915MHz
  Use Murata Wirewound inductors.
  For capacitors, use Johanson.
- RFIN_HARV
- ATMOSIC TECHNOLOGIES INC
- Atmosic Technologies Proprietary and Confidential
